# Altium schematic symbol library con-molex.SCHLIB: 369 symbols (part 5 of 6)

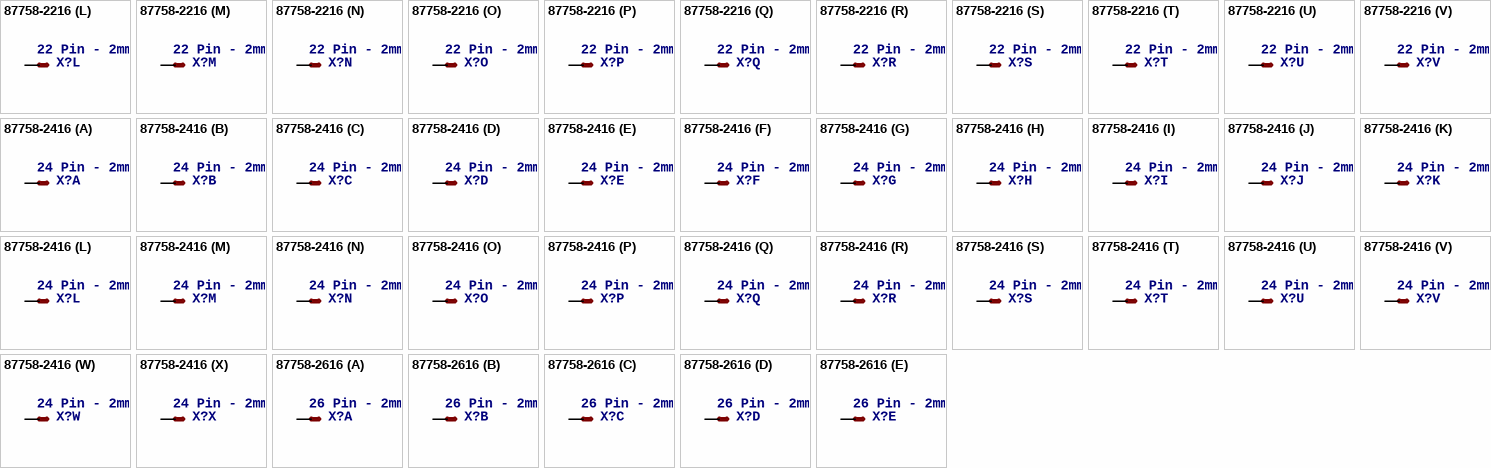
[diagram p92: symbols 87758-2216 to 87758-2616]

## 87758-2216
designator X?, comment 22 Pin - 2mm Dual Row Single Wafer, Vertical T/H HDR   Source: http://www.molex.com/pdm_docs/sd/877580616_sd.pdf
MPN: 87758-2216
footprint 87758-2216
part A pins: 1 S
part B pins: 2 S
part C pins: 3 S
part D pins: 4 S
part E pins: 5 S
part F pins: 6 S
part G pins: 7 S
part H pins: 8 S
part I pins: 9 S
part J pins: 10 S
part K pins: 11 S
part L pins: 12 S
part M pins: 13 S
part N pins: 14 S
part O pins: 15 S
part P pins: 16 S
part Q pins: 17 S
part R pins: 18 S
part S pins: 19 S
part T pins: 20 S
part U pins: 21 S
part V pins: 22 S

## 87758-2416
designator X?, comment 24 Pin - 2mm Dual Row Single Wafer, Vertical T/H HDR   Source: http://www.molex.com/pdm_docs/sd/877580616_sd.pdf
MPN: 87758-2416
footprint 87758-2416
part A pins: 1 S
part B pins: 2 S
part C pins: 3 S
part D pins: 4 S
part E pins: 5 S
part F pins: 6 S
part G pins: 7 S
part H pins: 8 S
part I pins: 9 S
part J pins: 10 S
part K pins: 11 S
part L pins: 12 S
part M pins: 13 S
part N pins: 14 S
part O pins: 15 S
part P pins: 16 S
part Q pins: 17 S
part R pins: 18 S
part S pins: 19 S
part T pins: 20 S
part U pins: 21 S
part V pins: 22 S
part W pins: 23 S
part X pins: 24 S

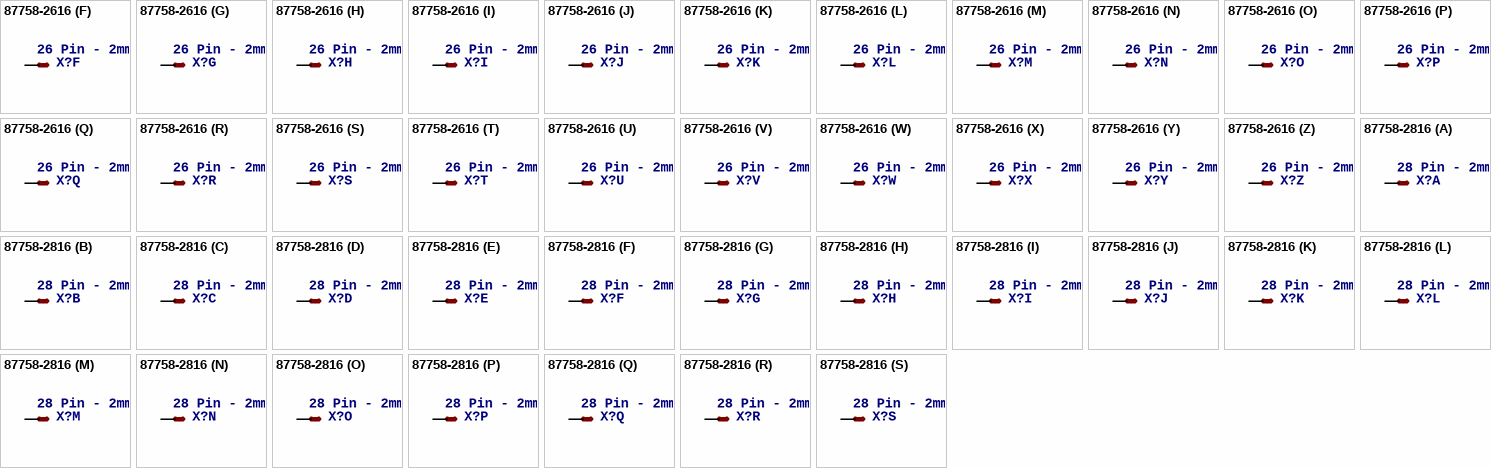
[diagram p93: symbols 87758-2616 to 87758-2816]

## 87758-2616
designator X?, comment 26 Pin - 2mm Dual Row Single Wafer, Vertical T/H HDR   Source: http://www.molex.com/pdm_docs/sd/877580616_sd.pdf
MPN: 87758-2616
footprint 87758-2616
part A pins: 1 S
part B pins: 2 S
part C pins: 3 S
part D pins: 4 S
part E pins: 5 S
part F pins: 6 S
part G pins: 7 S
part H pins: 8 S
part I pins: 9 S
part J pins: 10 S
part K pins: 11 S
part L pins: 12 S
part M pins: 13 S
part N pins: 14 S
part O pins: 15 S
part P pins: 16 S
part Q pins: 17 S
part R pins: 18 S
part S pins: 19 S
part T pins: 20 S
part U pins: 21 S
part V pins: 22 S
part W pins: 23 S
part X pins: 24 S
part Y pins: 25 S
part Z pins: 26 S

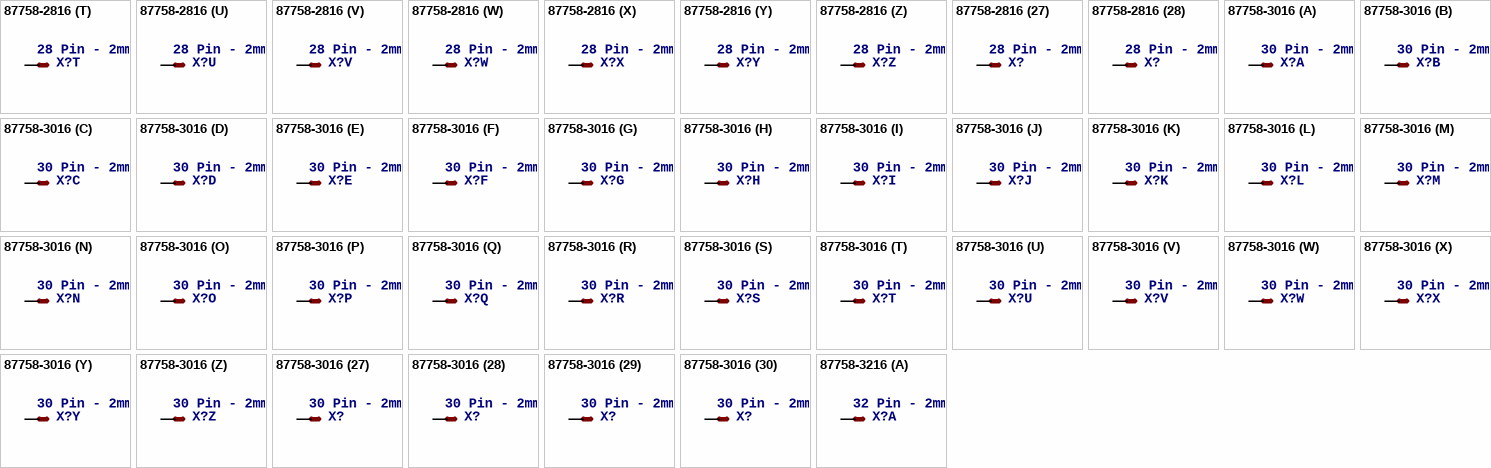
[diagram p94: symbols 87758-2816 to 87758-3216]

## 87758-2816
designator X?, comment 28 Pin - 2mm Dual Row Single Wafer, Vertical T/H HDR   Source: http://www.molex.com/pdm_docs/sd/877580616_sd.pdf
MPN: 87758-2816
footprint 87758-2816
part A pins: 1 S
part B pins: 2 S
part C pins: 3 S
part D pins: 4 S
part E pins: 5 S
part F pins: 6 S
part G pins: 7 S
part H pins: 8 S
part I pins: 9 S
part J pins: 10 S
part K pins: 11 S
part L pins: 12 S
part M pins: 13 S
part N pins: 14 S
part O pins: 15 S
part P pins: 16 S
part Q pins: 17 S
part R pins: 18 S
part S pins: 19 S
part T pins: 20 S
part U pins: 21 S
part V pins: 22 S
part W pins: 23 S
part X pins: 24 S
part Y pins: 25 S
part Z pins: 26 S
part 27 pins: 27 S
part 28 pins: 28 S

## 87758-3016
designator X?, comment 30 Pin - 2mm Dual Row Single Wafer, Vertical T/H HDR   Source: http://www.molex.com/pdm_docs/sd/877580616_sd.pdf
MPN: 87758-3016; MF: MOLEX
footprint 87758-3016
part A pins: 1 S
part B pins: 2 S
part C pins: 3 S
part D pins: 4 S
part E pins: 5 S
part F pins: 6 S
part G pins: 7 S
part H pins: 8 S
part I pins: 9 S
part J pins: 10 S
part K pins: 11 S
part L pins: 12 S
part M pins: 13 S
part N pins: 14 S
part O pins: 15 S
part P pins: 16 S
part Q pins: 17 S
part R pins: 18 S
part S pins: 19 S
part T pins: 20 S
part U pins: 21 S
part V pins: 22 S
part W pins: 23 S
part X pins: 24 S
part Y pins: 25 S
part Z pins: 26 S
part 27 pins: 27 S
part 28 pins: 28 S
part 29 pins: 29 S
part 30 pins: 30 S

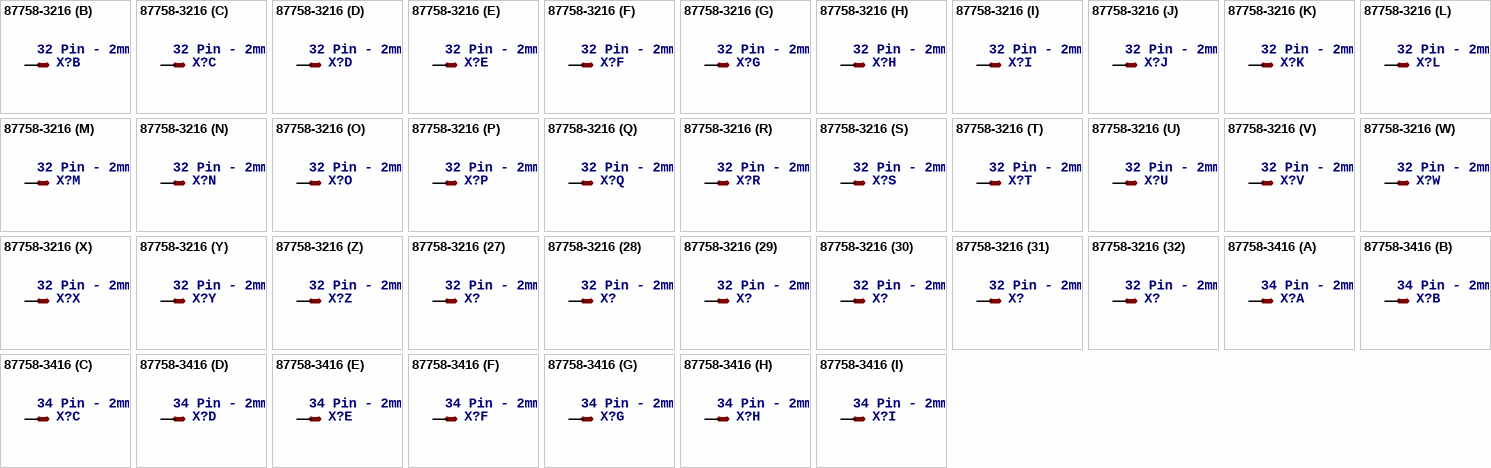
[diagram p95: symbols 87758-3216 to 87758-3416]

## 87758-3216
designator X?, comment 32 Pin - 2mm Dual Row Single Wafer, Vertical T/H HDR   Source: http://www.molex.com/pdm_docs/sd/877580616_sd.pdf
MPN: 87758-3216
footprint 87758-3216
part A pins: 1 S
part B pins: 2 S
part C pins: 3 S
part D pins: 4 S
part E pins: 5 S
part F pins: 6 S
part G pins: 7 S
part H pins: 8 S
part I pins: 9 S
part J pins: 10 S
part K pins: 11 S
part L pins: 12 S
part M pins: 13 S
part N pins: 14 S
part O pins: 15 S
part P pins: 16 S
part Q pins: 17 S
part R pins: 18 S
part S pins: 19 S
part T pins: 20 S
part U pins: 21 S
part V pins: 22 S
part W pins: 23 S
part X pins: 24 S
part Y pins: 25 S
part Z pins: 26 S
part 27 pins: 27 S
part 28 pins: 28 S
part 29 pins: 29 S
part 30 pins: 30 S
part 31 pins: 31 S
part 32 pins: 32 S

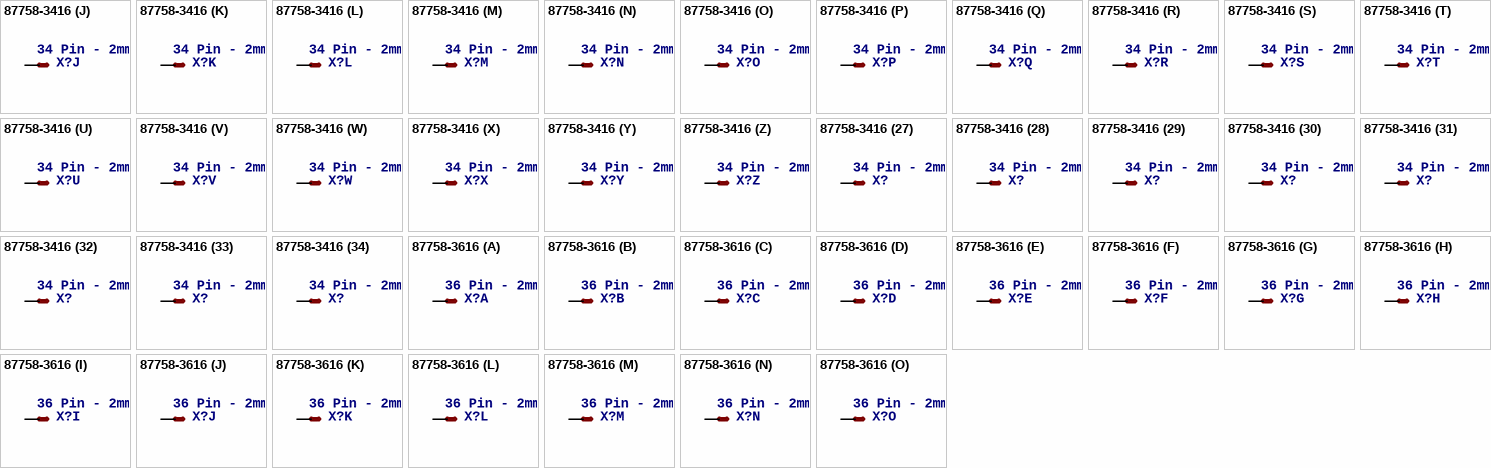
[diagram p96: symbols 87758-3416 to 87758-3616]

## 87758-3416
designator X?, comment 34 Pin - 2mm Dual Row Single Wafer, Vertical T/H HDR   Source: http://www.molex.com/pdm_docs/sd/877580616_sd.pdf
MPN: 87758-3416
footprint 87758-3416
part A pins: 1 S
part B pins: 2 S
part C pins: 3 S
part D pins: 4 S
part E pins: 5 S
part F pins: 6 S
part G pins: 7 S
part H pins: 8 S
part I pins: 9 S
part J pins: 10 S
part K pins: 11 S
part L pins: 12 S
part M pins: 13 S
part N pins: 14 S
part O pins: 15 S
part P pins: 16 S
part Q pins: 17 S
part R pins: 18 S
part S pins: 19 S
part T pins: 20 S
part U pins: 21 S
part V pins: 22 S
part W pins: 23 S
part X pins: 24 S
part Y pins: 25 S
part Z pins: 26 S
part 27 pins: 27 S
part 28 pins: 28 S
part 29 pins: 29 S
part 30 pins: 30 S
part 31 pins: 31 S
part 32 pins: 32 S
part 33 pins: 33 S
part 34 pins: 34 S

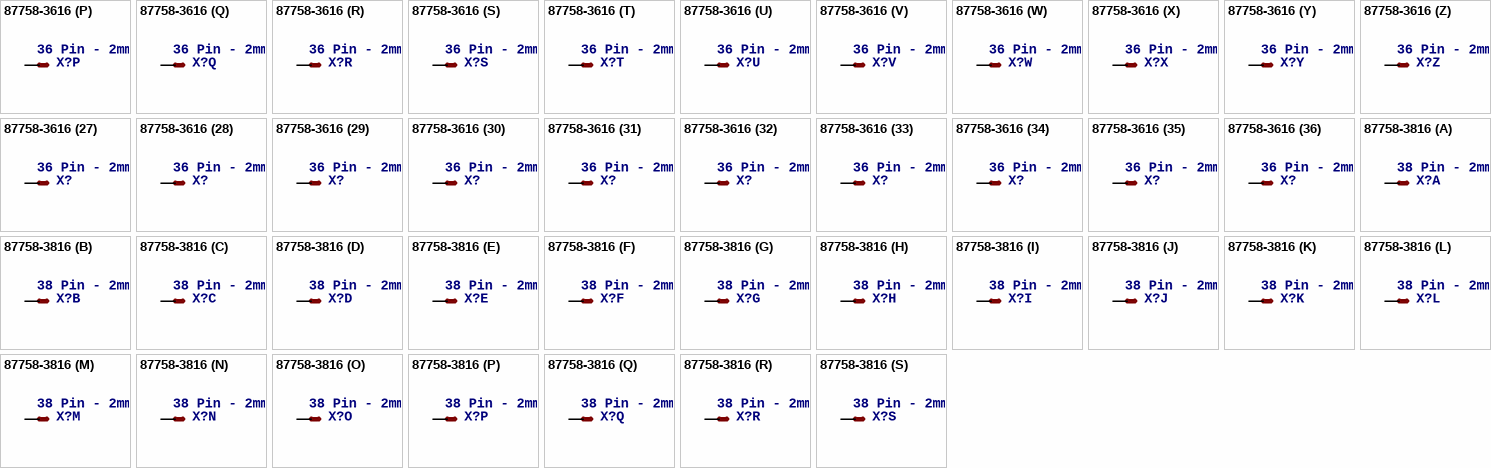
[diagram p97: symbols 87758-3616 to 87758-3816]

## 87758-3616
designator X?, comment 36 Pin - 2mm Dual Row Single Wafer, Vertical T/H HDR   Source: http://www.molex.com/pdm_docs/sd/877580616_sd.pdf
MPN: 87758-3616
footprint 87758-3616
part A pins: 1 S
part B pins: 2 S
part C pins: 3 S
part D pins: 4 S
part E pins: 5 S
part F pins: 6 S
part G pins: 7 S
part H pins: 8 S
part I pins: 9 S
part J pins: 10 S
part K pins: 11 S
part L pins: 12 S
part M pins: 13 S
part N pins: 14 S
part O pins: 15 S
part P pins: 16 S
part Q pins: 17 S
part R pins: 18 S
part S pins: 19 S
part T pins: 20 S
part U pins: 21 S
part V pins: 22 S
part W pins: 23 S
part X pins: 24 S
part Y pins: 25 S
part Z pins: 26 S
part 27 pins: 27 S
part 28 pins: 28 S
part 29 pins: 29 S
part 30 pins: 30 S
part 31 pins: 31 S
part 32 pins: 32 S
part 33 pins: 33 S
part 34 pins: 34 S
part 35 pins: 35 S
part 36 pins: 36 S

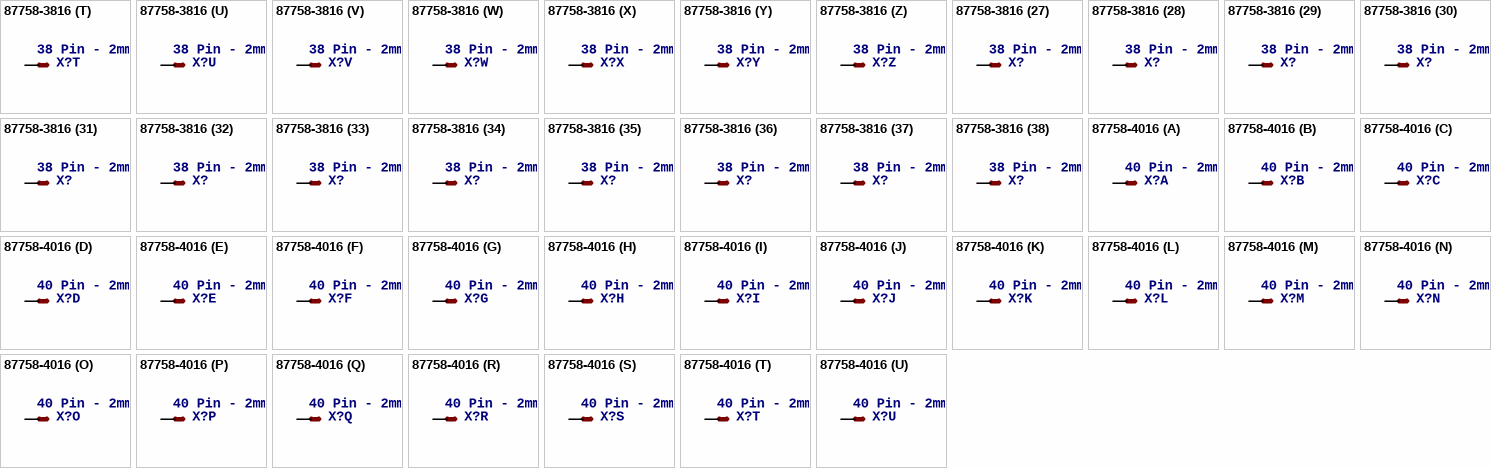
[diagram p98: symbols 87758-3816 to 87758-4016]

## 87758-3816
designator X?, comment 38 Pin - 2mm Dual Row Single Wafer, Vertical T/H HDR   Source: http://www.molex.com/pdm_docs/sd/877580616_sd.pdf
MPN: 87758-3816
footprint 87758-3816
part A pins: 1 S
part B pins: 2 S
part C pins: 3 S
part D pins: 4 S
part E pins: 5 S
part F pins: 6 S
part G pins: 7 S
part H pins: 8 S
part I pins: 9 S
part J pins: 10 S
part K pins: 11 S
part L pins: 12 S
part M pins: 13 S
part N pins: 14 S
part O pins: 15 S
part P pins: 16 S
part Q pins: 17 S
part R pins: 18 S
part S pins: 19 S
part T pins: 20 S
part U pins: 21 S
part V pins: 22 S
part W pins: 23 S
part X pins: 24 S
part Y pins: 25 S
part Z pins: 26 S
part 27 pins: 27 S
part 28 pins: 28 S
part 29 pins: 29 S
part 30 pins: 30 S
part 31 pins: 31 S
part 32 pins: 32 S
part 33 pins: 33 S
part 34 pins: 34 S
part 35 pins: 35 S
part 36 pins: 36 S
part 37 pins: 37 S
part 38 pins: 38 S

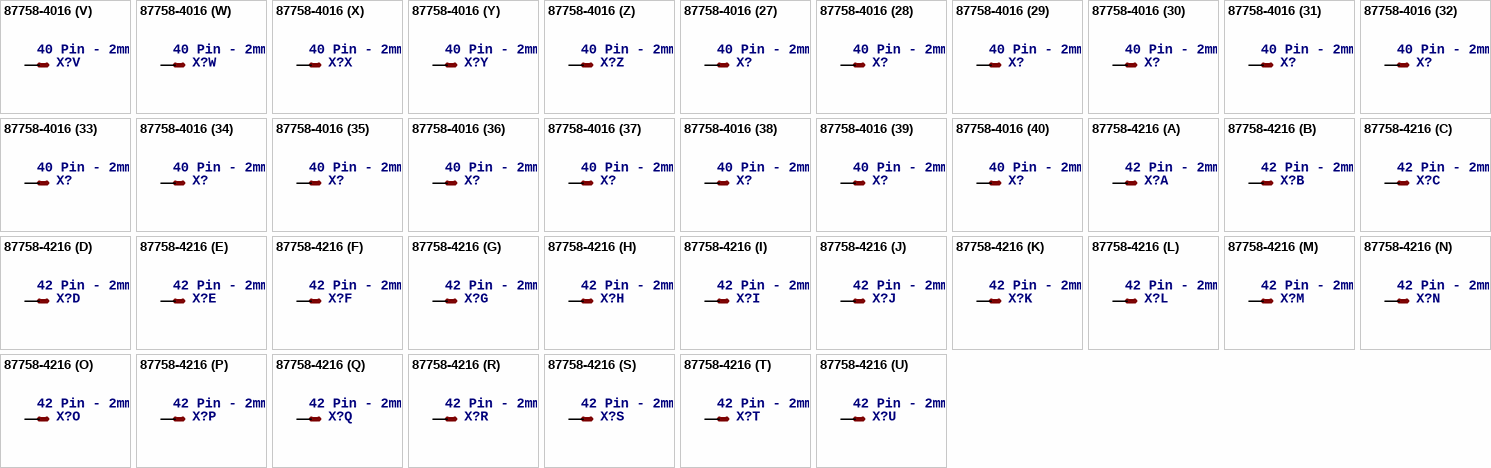
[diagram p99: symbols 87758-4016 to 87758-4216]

## 87758-4016
designator X?, comment 40 Pin - 2mm Dual Row Single Wafer, Vertical T/H HDR   Source: http://www.molex.com/pdm_docs/sd/877580616_sd.pdf
MPN: 87758-4016
footprint 87758-4016
part A pins: 1 S
part B pins: 2 S
part C pins: 3 S
part D pins: 4 S
part E pins: 5 S
part F pins: 6 S
part G pins: 7 S
part H pins: 8 S
part I pins: 9 S
part J pins: 10 S
part K pins: 11 S
part L pins: 12 S
part M pins: 13 S
part N pins: 14 S
part O pins: 15 S
part P pins: 16 S
part Q pins: 17 S
part R pins: 18 S
part S pins: 19 S
part T pins: 20 S
part U pins: 21 S
part V pins: 22 S
part W pins: 23 S
part X pins: 24 S
part Y pins: 25 S
part Z pins: 26 S
part 27 pins: 27 S
part 28 pins: 28 S
part 29 pins: 29 S
part 30 pins: 30 S
part 31 pins: 31 S
part 32 pins: 32 S
part 33 pins: 33 S
part 34 pins: 34 S
part 35 pins: 35 S
part 36 pins: 36 S
part 37 pins: 37 S
part 38 pins: 38 S
part 39 pins: 39 S
part 40 pins: 40 S

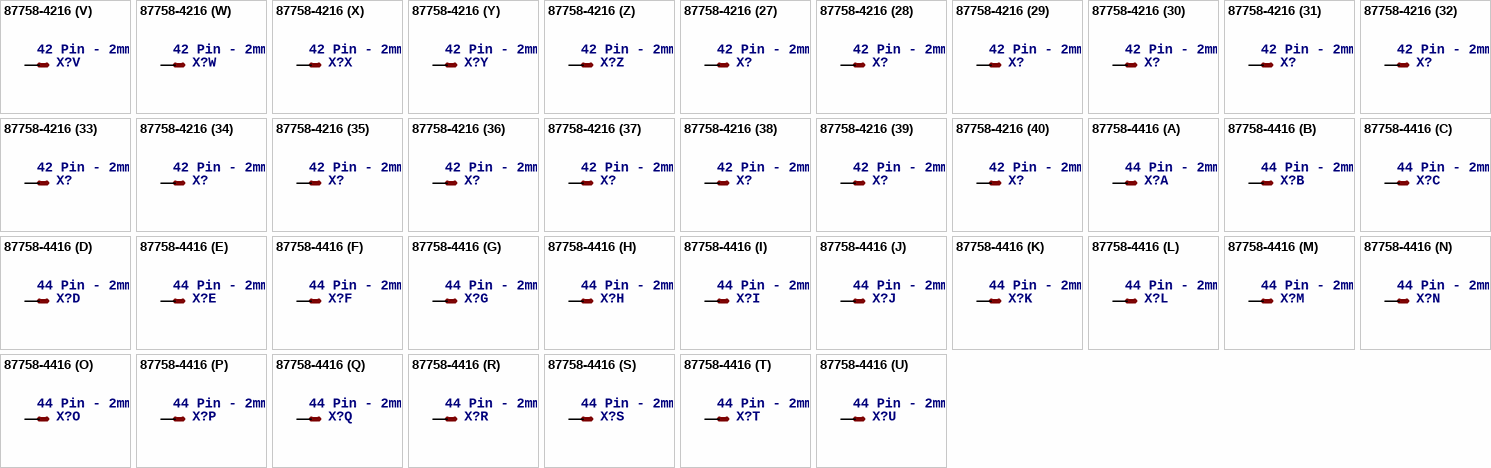
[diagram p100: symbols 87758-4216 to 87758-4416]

## 87758-4216
designator X?, comment 42 Pin - 2mm Dual Row Single Wafer, Vertical T/H HDR   Source: http://www.molex.com/pdm_docs/sd/877580616_sd.pdf
MPN: 87758-4216
footprint 87758-4216
part A pins: 1 S
part B pins: 2 S
part C pins: 3 S
part D pins: 4 S
part E pins: 5 S
part F pins: 6 S
part G pins: 7 S
part H pins: 8 S
part I pins: 9 S
part J pins: 10 S
part K pins: 11 S
part L pins: 12 S
part M pins: 13 S
part N pins: 14 S
part O pins: 15 S
part P pins: 16 S
part Q pins: 17 S
part R pins: 18 S
part S pins: 19 S
part T pins: 20 S
part U pins: 21 S
part V pins: 22 S
part W pins: 23 S
part X pins: 24 S
part Y pins: 25 S
part Z pins: 26 S
part 27 pins: 27 S
part 28 pins: 28 S
part 29 pins: 29 S
part 30 pins: 30 S
part 31 pins: 31 S
part 32 pins: 32 S
part 33 pins: 33 S
part 34 pins: 34 S
part 35 pins: 35 S
part 36 pins: 36 S
part 37 pins: 37 S
part 38 pins: 38 S
part 39 pins: 39 S
part 40 pins: 40 S
part 41 pins: 41 S
part 42 pins: 42 S

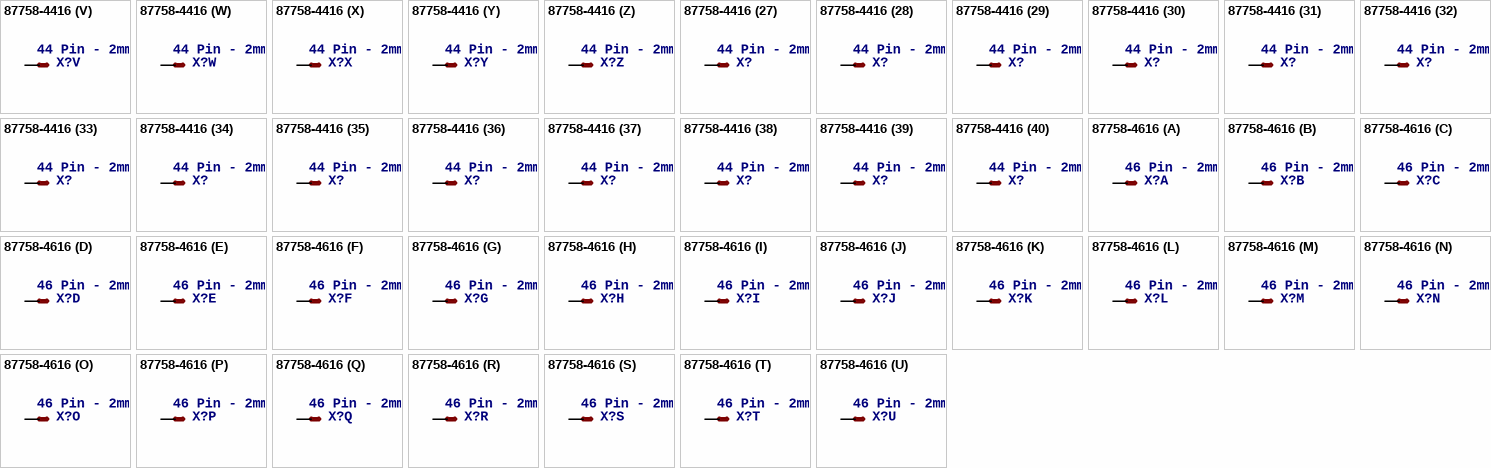
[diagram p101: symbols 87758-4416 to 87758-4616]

## 87758-4416
designator X?, comment 44 Pin - 2mm Dual Row Single Wafer, Vertical T/H HDR   Source: http://www.molex.com/pdm_docs/sd/877580616_sd.pdf
MPN: 87758-4416; MF: MOLEX
footprint 87758-4416
part A pins: 1 S
part B pins: 2 S
part C pins: 3 S
part D pins: 4 S
part E pins: 5 S
part F pins: 6 S
part G pins: 7 S
part H pins: 8 S
part I pins: 9 S
part J pins: 10 S
part K pins: 11 S
part L pins: 12 S
part M pins: 13 S
part N pins: 14 S
part O pins: 15 S
part P pins: 16 S
part Q pins: 17 S
part R pins: 18 S
part S pins: 19 S
part T pins: 20 S
part U pins: 21 S
part V pins: 22 S
part W pins: 23 S
part X pins: 24 S
part Y pins: 25 S
part Z pins: 26 S
part 27 pins: 27 S
part 28 pins: 28 S
part 29 pins: 29 S
part 30 pins: 30 S
part 31 pins: 31 S
part 32 pins: 32 S
part 33 pins: 33 S
part 34 pins: 34 S
part 35 pins: 35 S
part 36 pins: 36 S
part 37 pins: 37 S
part 38 pins: 38 S
part 39 pins: 39 S
part 40 pins: 40 S
part 41 pins: 41 S
part 42 pins: 42 S
part 43 pins: 43 S
part 44 pins: 44 S

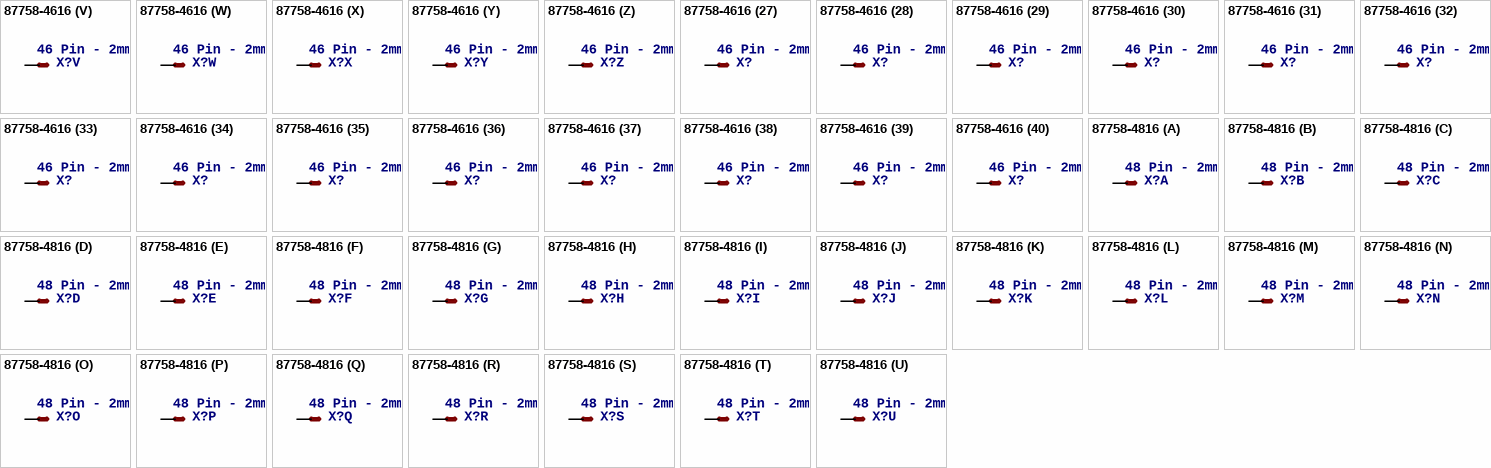
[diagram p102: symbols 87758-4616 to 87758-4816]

## 87758-4616
designator X?, comment 46 Pin - 2mm Dual Row Single Wafer, Vertical T/H HDR   Source: http://www.molex.com/pdm_docs/sd/877580616_sd.pdf
MPN: 87758-4616
footprint 87758-4616
part A pins: 1 S
part B pins: 2 S
part C pins: 3 S
part D pins: 4 S
part E pins: 5 S
part F pins: 6 S
part G pins: 7 S
part H pins: 8 S
part I pins: 9 S
part J pins: 10 S
part K pins: 11 S
part L pins: 12 S
part M pins: 13 S
part N pins: 14 S
part O pins: 15 S
part P pins: 16 S
part Q pins: 17 S
part R pins: 18 S
part S pins: 19 S
part T pins: 20 S
part U pins: 21 S
part V pins: 22 S
part W pins: 23 S
part X pins: 24 S
part Y pins: 25 S
part Z pins: 26 S
part 27 pins: 27 S
part 28 pins: 28 S
part 29 pins: 29 S
part 30 pins: 30 S
part 31 pins: 31 S
part 32 pins: 32 S
part 33 pins: 33 S
part 34 pins: 34 S
part 35 pins: 35 S
part 36 pins: 36 S
part 37 pins: 37 S
part 38 pins: 38 S
part 39 pins: 39 S
part 40 pins: 40 S
part 41 pins: 41 S
part 42 pins: 42 S
part 43 pins: 43 S
part 44 pins: 44 S
part 45 pins: 45 S
part 46 pins: 46 S

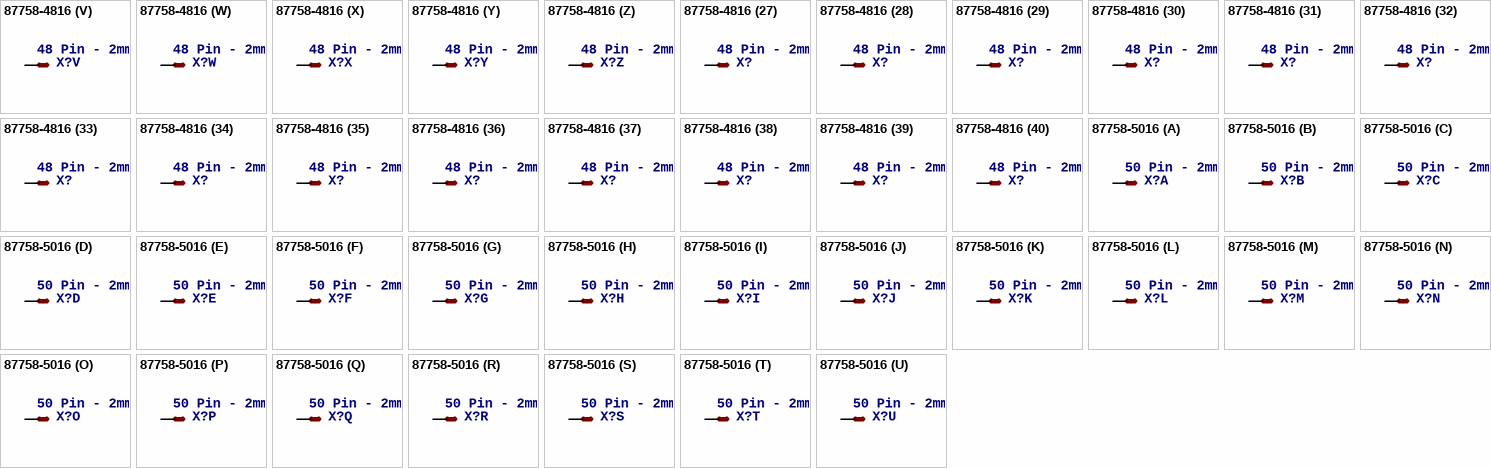
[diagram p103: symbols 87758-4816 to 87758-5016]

## 87758-4816
designator X?, comment 48 Pin - 2mm Dual Row Single Wafer, Vertical T/H HDR   Source: http://www.molex.com/pdm_docs/sd/877580616_sd.pdf
MPN: 87758-4816
footprint 87758-4816
part A pins: 1 S
part B pins: 2 S
part C pins: 3 S
part D pins: 4 S
part E pins: 5 S
part F pins: 6 S
part G pins: 7 S
part H pins: 8 S
part I pins: 9 S
part J pins: 10 S
part K pins: 11 S
part L pins: 12 S
part M pins: 13 S
part N pins: 14 S
part O pins: 15 S
part P pins: 16 S
part Q pins: 17 S
part R pins: 18 S
part S pins: 19 S
part T pins: 20 S
part U pins: 21 S
part V pins: 22 S
part W pins: 23 S
part X pins: 24 S
part Y pins: 25 S
part Z pins: 26 S
part 27 pins: 27 S
part 28 pins: 28 S
part 29 pins: 29 S
part 30 pins: 30 S
part 31 pins: 31 S
part 32 pins: 32 S
part 33 pins: 33 S
part 34 pins: 34 S
part 35 pins: 35 S
part 36 pins: 36 S
part 37 pins: 37 S
part 38 pins: 38 S
part 39 pins: 39 S
part 40 pins: 40 S
part 41 pins: 41 S
part 42 pins: 42 S
part 43 pins: 43 S
part 44 pins: 44 S
part 45 pins: 45 S
part 46 pins: 46 S
part 47 pins: 47 S
part 48 pins: 48 S

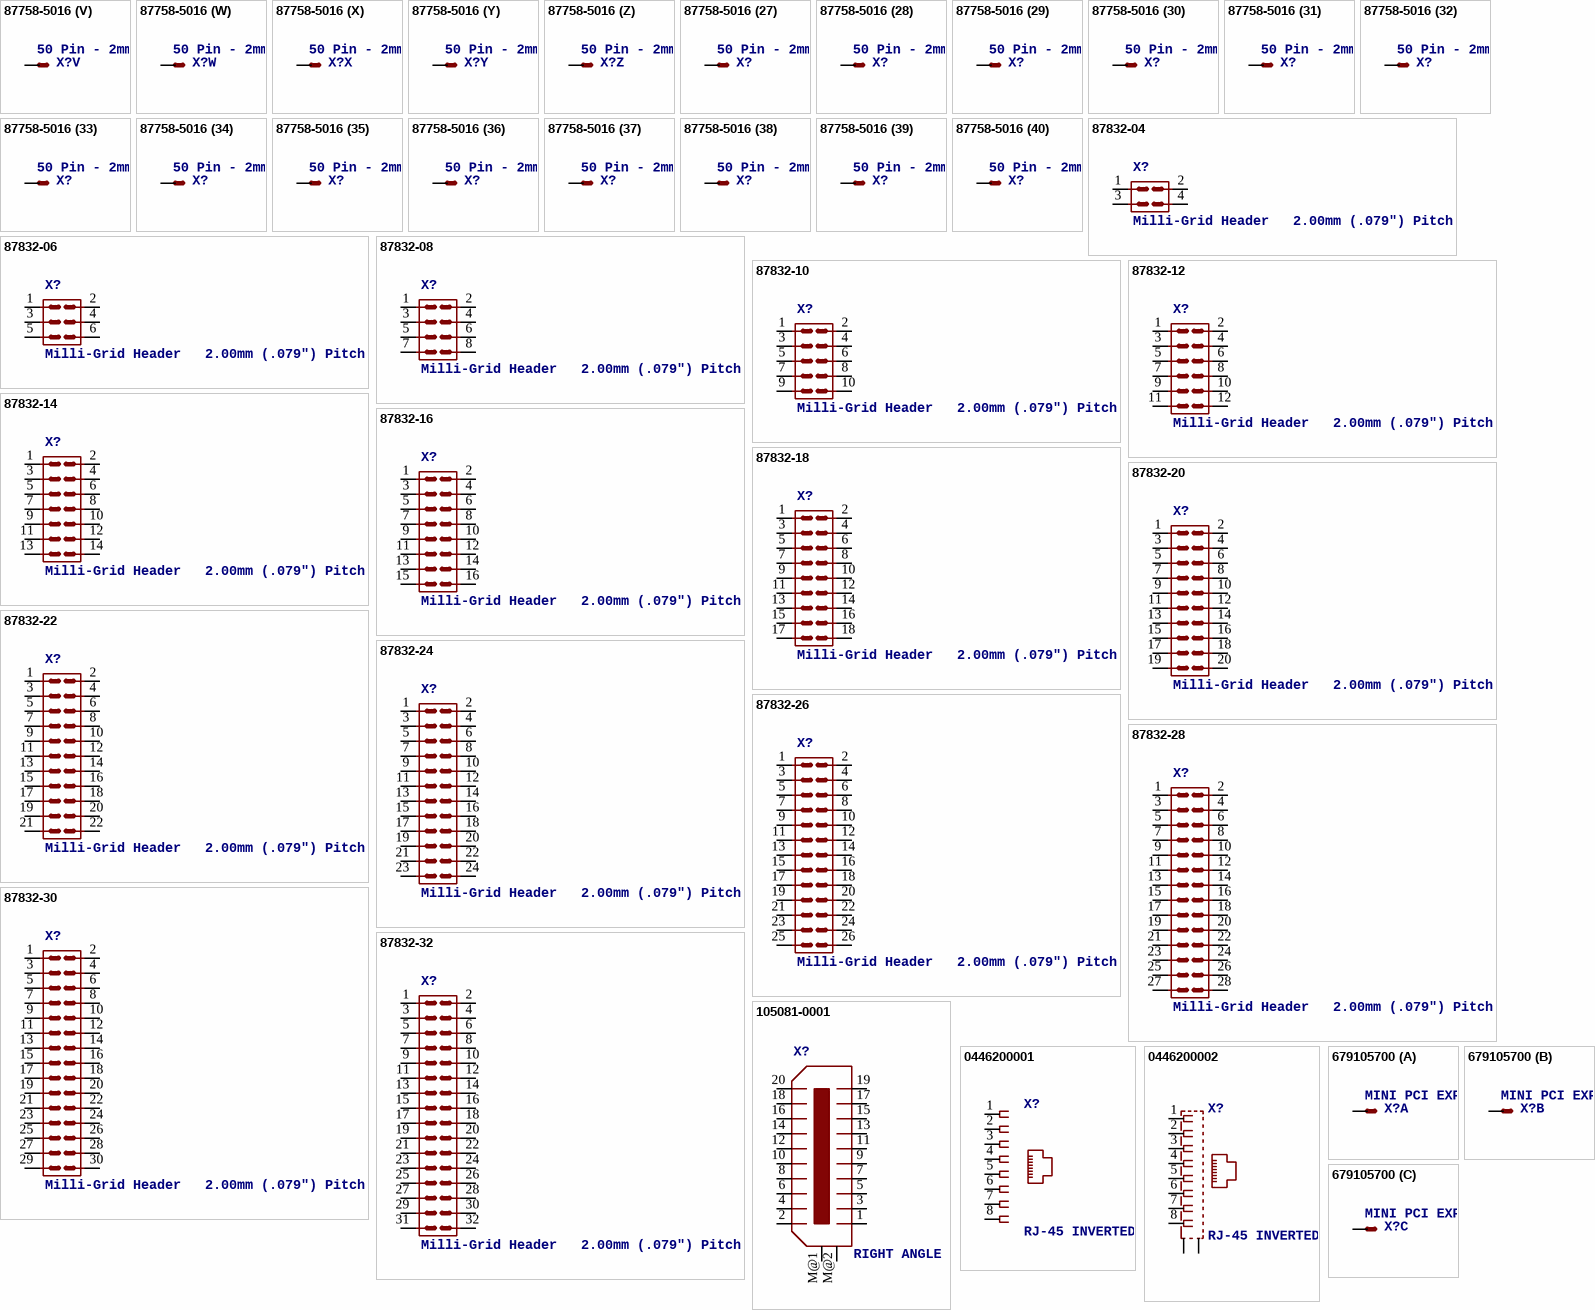
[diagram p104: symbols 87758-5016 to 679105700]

## 87758-5016
designator X?, comment 50 Pin - 2mm Dual Row Single Wafer, Vertical T/H HDR   Source: http://www.molex.com/pdm_docs/sd/877580616_sd.pdf
MPN: 87758-5016; MF: MOLEX
footprint 87758-5016
part A pins: 1 S
part B pins: 2 S
part C pins: 3 S
part D pins: 4 S
part E pins: 5 S
part F pins: 6 S
part G pins: 7 S
part H pins: 8 S
part I pins: 9 S
part J pins: 10 S
part K pins: 11 S
part L pins: 12 S
part M pins: 13 S
part N pins: 14 S
part O pins: 15 S
part P pins: 16 S
part Q pins: 17 S
part R pins: 18 S
part S pins: 19 S
part T pins: 20 S
part U pins: 21 S
part V pins: 22 S
part W pins: 23 S
part X pins: 24 S
part Y pins: 25 S
part Z pins: 26 S
part 27 pins: 27 S
part 28 pins: 28 S
part 29 pins: 29 S
part 30 pins: 30 S
part 31 pins: 31 S
part 32 pins: 32 S
part 33 pins: 33 S
part 34 pins: 34 S
part 35 pins: 35 S
part 36 pins: 36 S
part 37 pins: 37 S
part 38 pins: 38 S
part 39 pins: 39 S
part 40 pins: 40 S
part 41 pins: 41 S
part 42 pins: 42 S
part 43 pins: 43 S
part 44 pins: 44 S
part 45 pins: 45 S
part 46 pins: 46 S
part 47 pins: 47 S
part 48 pins: 48 S
part 49 pins: 49 S
part 50 pins: 50 S

## 87832-04
designator X?, comment Milli-Grid Header   2.00mm (.079") Pitch
footprint 87832-04
pins: 1, 2, 3, 4

## 87832-06
designator X?, comment Milli-Grid Header   2.00mm (.079") Pitch
footprint 87832-06
pins: 1, 2, 3, 4, 5, 6

## 87832-08
designator X?, comment Milli-Grid Header   2.00mm (.079") Pitch
footprint 87832-08
pins: 1, 2, 3, 4, 5, 6, 7, 8

## 87832-10
designator X?, comment Milli-Grid Header   2.00mm (.079") Pitch
footprint 87832-10
pins: 1, 2, 3, 4, 5, 6, 7, 8, 9, 10

## 87832-12
designator X?, comment Milli-Grid Header   2.00mm (.079") Pitch
footprint 87832-12
pins: 1, 2, 3, 4, 5, 6, 7, 8, 9, 10, 11, 12

## 87832-14
designator X?, comment Milli-Grid Header   2.00mm (.079") Pitch
footprint 87832-14
pins: 1, 2, 3, 4, 5, 6, 7, 8, 9, 10, 11, 12, 13, 14

## 87832-16
designator X?, comment Milli-Grid Header   2.00mm (.079") Pitch
footprint 87832-16
pins: 1, 2, 3, 4, 5, 6, 7, 8, 9, 10, 11, 12, 13, 14, 15, 16

## 87832-18
designator X?, comment Milli-Grid Header   2.00mm (.079") Pitch
footprint 87832-18
pins: 1, 2, 3, 4, 5, 6, 7, 8, 9, 10, 11, 12, 13, 14, 15, 16, 17, 18

## 87832-20
designator X?, comment Milli-Grid Header   2.00mm (.079") Pitch
footprint 87832-20
pins: 1, 2, 3, 4, 5, 6, 7, 8, 9, 10, 11, 12, 13, 14, 15, 16, 17, 18, 19, 20

## 87832-22
designator X?, comment Milli-Grid Header   2.00mm (.079") Pitch
footprint 87832-22
pins: 1, 2, 3, 4, 5, 6, 7, 8, 9, 10, 11, 12, 13, 14, 15, 16, 17, 18, 19, 20, 21, 22

## 87832-24
designator X?, comment Milli-Grid Header   2.00mm (.079") Pitch
footprint 87832-24
pins: 1, 2, 3, 4, 5, 6, 7, 8, 9, 10, 11, 12, 13, 14, 15, 16, 17, 18, 19, 20, 21, 22, 23, 24

## 87832-26
designator X?, comment Milli-Grid Header   2.00mm (.079") Pitch
footprint 87832-26
pins: 1, 2, 3, 4, 5, 6, 7, 8, 9, 10, 11, 12, 13, 14, 15, 16, 17, 18, 19, 20, 21, 22, 23, 24, 25, 26

## 87832-28
designator X?, comment Milli-Grid Header   2.00mm (.079") Pitch
MPN: 87832-2821
footprint 87832-28
pins: 1, 2, 3, 4, 5, 6, 7, 8, 9, 10, 11, 12, 13, 14, 15, 16, 17, 18, 19, 20, 21, 22, 23, 24, 25, 26, 27, 28

## 87832-30
designator X?, comment Milli-Grid Header   2.00mm (.079") Pitch
footprint 87832-30
pins: 1, 2, 3, 4, 5, 6, 7, 8, 9, 10, 11, 12, 13, 14, 15, 16, 17, 18, 19, 20, 21, 22, 23, 24, 25, 26, 27, 28, 29, 30

## 87832-32
designator X?, comment Milli-Grid Header   2.00mm (.079") Pitch
footprint 87832-32
pins: 1, 2, 3, 4, 5, 6, 7, 8, 9, 10, 11, 12, 13, 14, 15, 16, 17, 18, 19, 20, 21, 22, 23, 24, 25, 26, 27, 28, 29, 30, 31, 32

## 105081-0001
designator X?, comment RIGHT ANGLE MINI-DISPLAYPORT RECEPTACLE   Source: http://www.molex.com/pdm_docs/sd/1050810001_sd.pdf
MPN: 105081-0001
footprint 105081-0001
pins: 1, 2, 3, 4, 5, 6, 7, 8, 9, 10, 11, 12, 13, 14, 15, 16, 17, 18, 19, 20, M@1, M@2

## 0446200001
designator X?, comment RJ-45 INVERTED MODULAR JACK ASSEMBLY WITH RJ-11 KEEPOUT FEATURE   Source:  Data sheet
footprint 0446200001
pins: 1, 2, 3, 4, 5, 6, 7, 8

## 0446200002
designator X?, comment RJ-45 INVERTED MODULAR JACK ASSEMBLY WITH RJ-11 KEEPOUT FEATURE   Source:  Data sheet    MOLEX  0446200002  BUCHSE, RJ45, GESCHIRMT    Source:
footprint 0446200002
pins: 1, 2, 3, 4, 5, 6, 7, 8, S@1 S1, S@2 S2

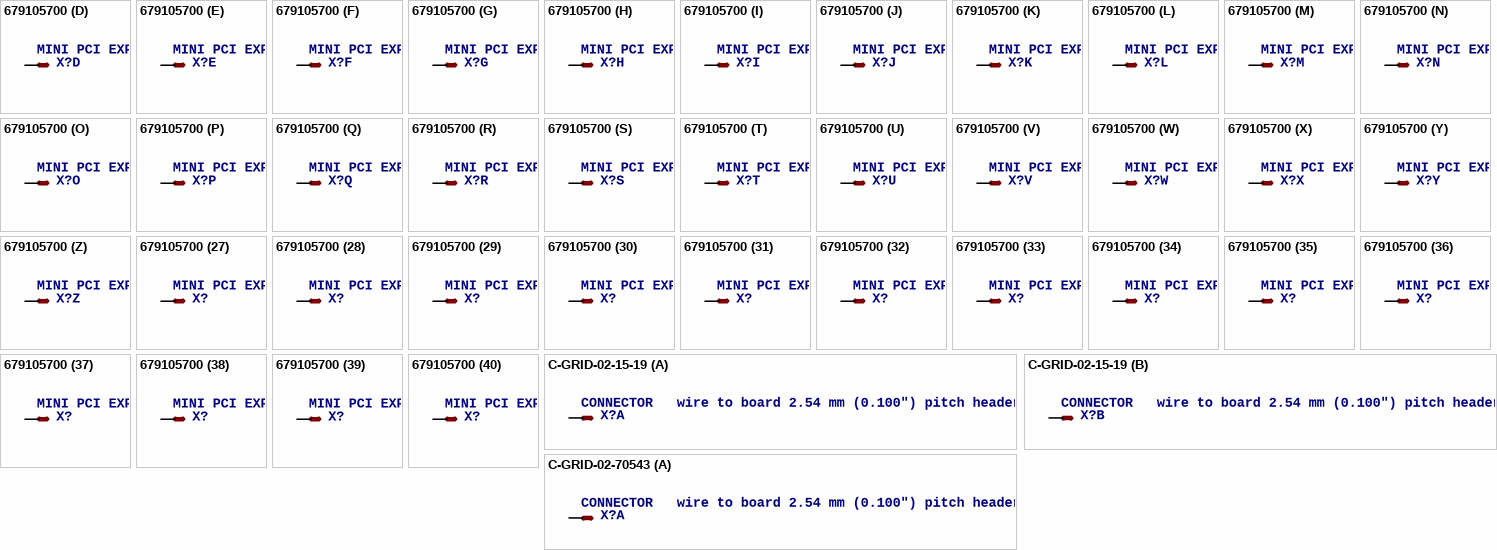
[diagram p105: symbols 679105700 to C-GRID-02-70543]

## 679105700
designator X?, comment MINI PCI EXPRESS CONNECTOR 0.8MM PITCH, 52 CIRCUIT   Source: http://www.molex.com/pdm_docs/sd/679105700_sd.pdf
MPN: 67910-5700
footprint 679105700
part A pins: 1 S
part B pins: 2 S
part C pins: 3 S
part D pins: 4 S
part E pins: 5 S
part F pins: 6 S
part G pins: 7 S
part H pins: 8 S
part I pins: 9 S
part J pins: 10 S
part K pins: 11 S
part L pins: 12 S
part M pins: 13 S
part N pins: 14 S
part O pins: 15 S
part P pins: 16 S
part Q pins: 17 S
part R pins: 18 S
part S pins: 19 S
part T pins: 20 S
part U pins: 21 S
part V pins: 22 S
part W pins: 23 S
part X pins: 24 S
part Y pins: 25 S
part Z pins: 26 S
part 27 pins: 27 S
part 28 pins: 28 S
part 29 pins: 29 S
part 30 pins: 30 S
part 31 pins: 31 S
part 32 pins: 32 S
part 33 pins: 33 S
part 34 pins: 34 S
part 35 pins: 35 S
part 36 pins: 36 S
part 37 pins: 37 S
part 38 pins: 38 S
part 39 pins: 39 S
part 40 pins: 40 S
part 41 pins: 41 S
part 42 pins: 42 S
part 43 pins: 43 S
part 44 pins: 44 S
part 45 pins: 45 S
part 46 pins: 46 S
part 47 pins: 47 S
part 48 pins: 48 S
part 49 pins: 49 S
part 50 pins: 50 S
part 51 pins: 51 S
part 52 pins: 52 S

## C-GRID-02-15-19
designator X?, comment CONNECTOR   wire to board 2.54 mm (0.100") pitch header
footprint 15-91-02
part A pins: 2 S
part B pins: 1 S

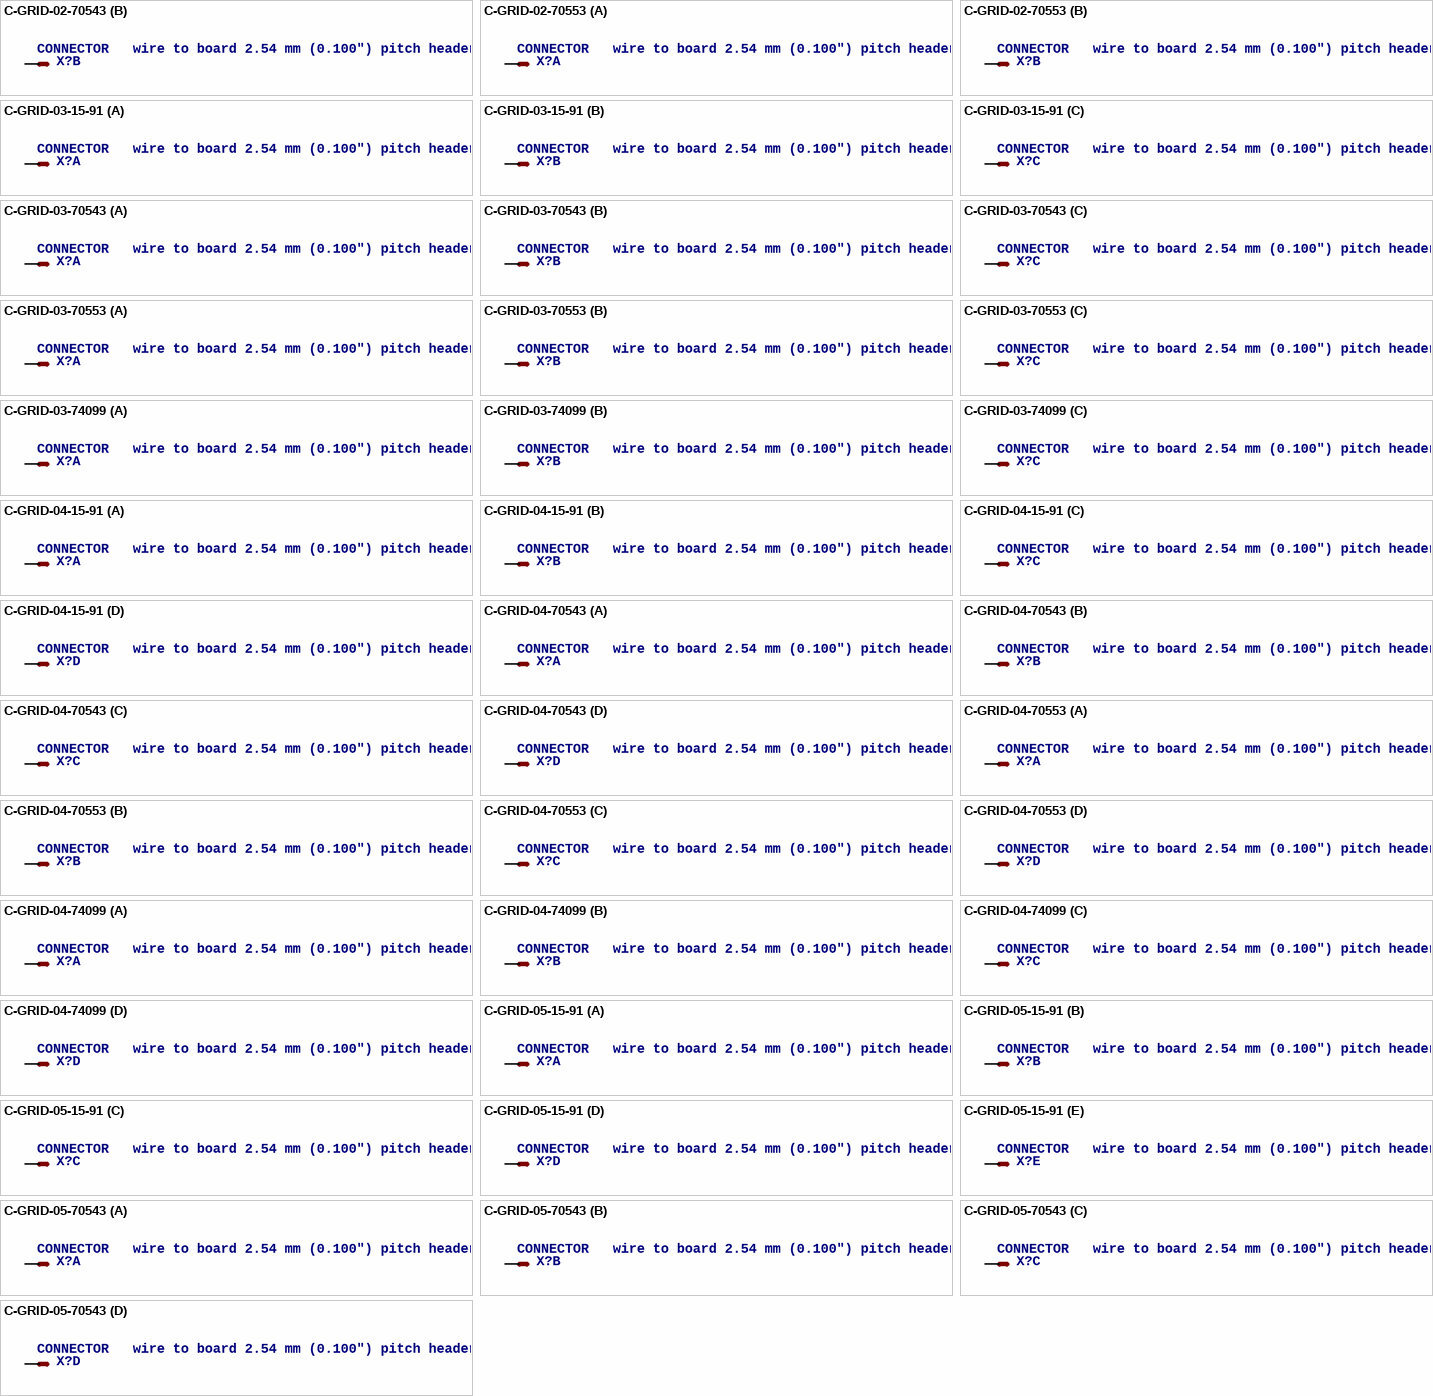
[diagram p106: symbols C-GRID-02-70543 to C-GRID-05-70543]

## C-GRID-02-70543
designator X?, comment CONNECTOR   wire to board 2.54 mm (0.100") pitch header
footprint 70543-02
part A pins: 2 S
part B pins: 1 S

## C-GRID-02-70553
designator X?, comment CONNECTOR   wire to board 2.54 mm (0.100") pitch header
footprint 70553-02
part A pins: 2 S
part B pins: 1 S

## C-GRID-03-15-91
designator X?, comment CONNECTOR   wire to board 2.54 mm (0.100") pitch header
footprint 15-91-03
part A pins: 1 S
part B pins: 2 S
part C pins: 3 S

## C-GRID-03-70543
designator X?, comment CONNECTOR   wire to board 2.54 mm (0.100") pitch header
footprint 70543-03
part A pins: 1 S
part B pins: 2 S
part C pins: 3 S

## C-GRID-03-70553
designator X?, comment CONNECTOR   wire to board 2.54 mm (0.100") pitch header
footprint 70553-03
part A pins: 1 S
part B pins: 2 S
part C pins: 3 S

## C-GRID-03-74099
designator X?, comment CONNECTOR   wire to board 2.54 mm (0.100") pitch header
footprint 74099-03
part A pins: 1 S
part B pins: 2 S
part C pins: 3 S

## C-GRID-04-15-91
designator X?, comment CONNECTOR   wire to board 2.54 mm (0.100") pitch header
footprint 15-91-04
part A pins: 1 S
part B pins: 2 S
part C pins: 3 S
part D pins: 4 S

## C-GRID-04-70543
designator X?, comment CONNECTOR   wire to board 2.54 mm (0.100") pitch header
footprint 70543-04
part A pins: 1 S
part B pins: 2 S
part C pins: 3 S
part D pins: 4 S

## C-GRID-04-70553
designator X?, comment CONNECTOR   wire to board 2.54 mm (0.100") pitch header
footprint 70553-04
part A pins: 1 S
part B pins: 2 S
part C pins: 3 S
part D pins: 4 S

## C-GRID-04-74099
designator X?, comment CONNECTOR   wire to board 2.54 mm (0.100") pitch header
footprint 74099-04
part A pins: 1 S
part B pins: 2 S
part C pins: 3 S
part D pins: 4 S

## C-GRID-05-15-91
designator X?, comment CONNECTOR   wire to board 2.54 mm (0.100") pitch header
footprint 15-91-05
part A pins: 1 S
part B pins: 2 S
part C pins: 3 S
part D pins: 4 S
part E pins: 5 S

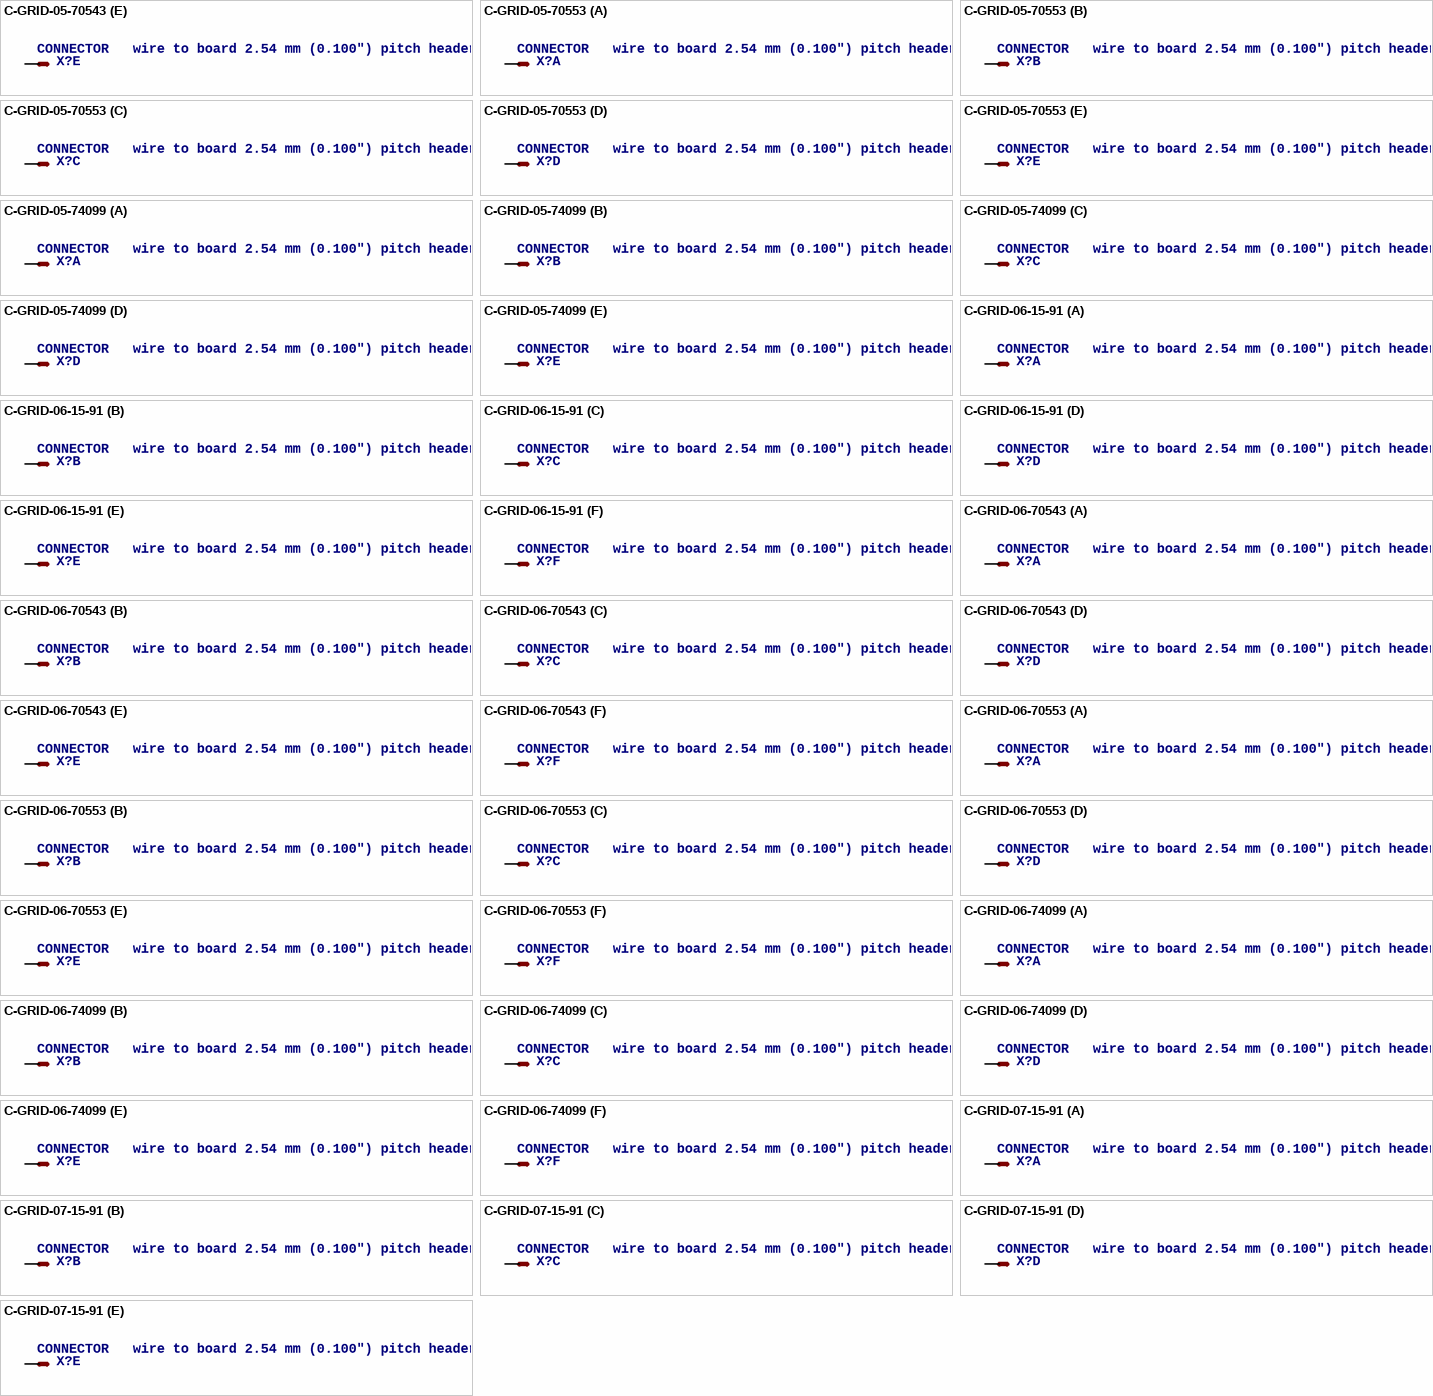
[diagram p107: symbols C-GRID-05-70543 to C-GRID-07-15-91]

## C-GRID-05-70543
designator X?, comment CONNECTOR   wire to board 2.54 mm (0.100") pitch header
footprint 70543-05
part A pins: 1 S
part B pins: 2 S
part C pins: 3 S
part D pins: 4 S
part E pins: 5 S

## C-GRID-05-70553
designator X?, comment CONNECTOR   wire to board 2.54 mm (0.100") pitch header
footprint 70553-05
part A pins: 1 S
part B pins: 2 S
part C pins: 3 S
part D pins: 4 S
part E pins: 5 S

## C-GRID-05-74099
designator X?, comment CONNECTOR   wire to board 2.54 mm (0.100") pitch header
footprint 74099-05
part A pins: 1 S
part B pins: 2 S
part C pins: 3 S
part D pins: 4 S
part E pins: 5 S

## C-GRID-06-15-91
designator X?, comment CONNECTOR   wire to board 2.54 mm (0.100") pitch header
footprint 15-91-06
part A pins: 1 S
part B pins: 2 S
part C pins: 3 S
part D pins: 4 S
part E pins: 5 S
part F pins: 6 S

## C-GRID-06-70543
designator X?, comment CONNECTOR   wire to board 2.54 mm (0.100") pitch header
footprint 70543-06
part A pins: 1 S
part B pins: 2 S
part C pins: 3 S
part D pins: 4 S
part E pins: 5 S
part F pins: 6 S

## C-GRID-06-70553
designator X?, comment CONNECTOR   wire to board 2.54 mm (0.100") pitch header
footprint 70553-06
part A pins: 1 S
part B pins: 2 S
part C pins: 3 S
part D pins: 4 S
part E pins: 5 S
part F pins: 6 S

## C-GRID-06-74099
designator X?, comment CONNECTOR   wire to board 2.54 mm (0.100") pitch header
footprint 74099-06
part A pins: 1 S
part B pins: 2 S
part C pins: 3 S
part D pins: 4 S
part E pins: 5 S
part F pins: 6 S

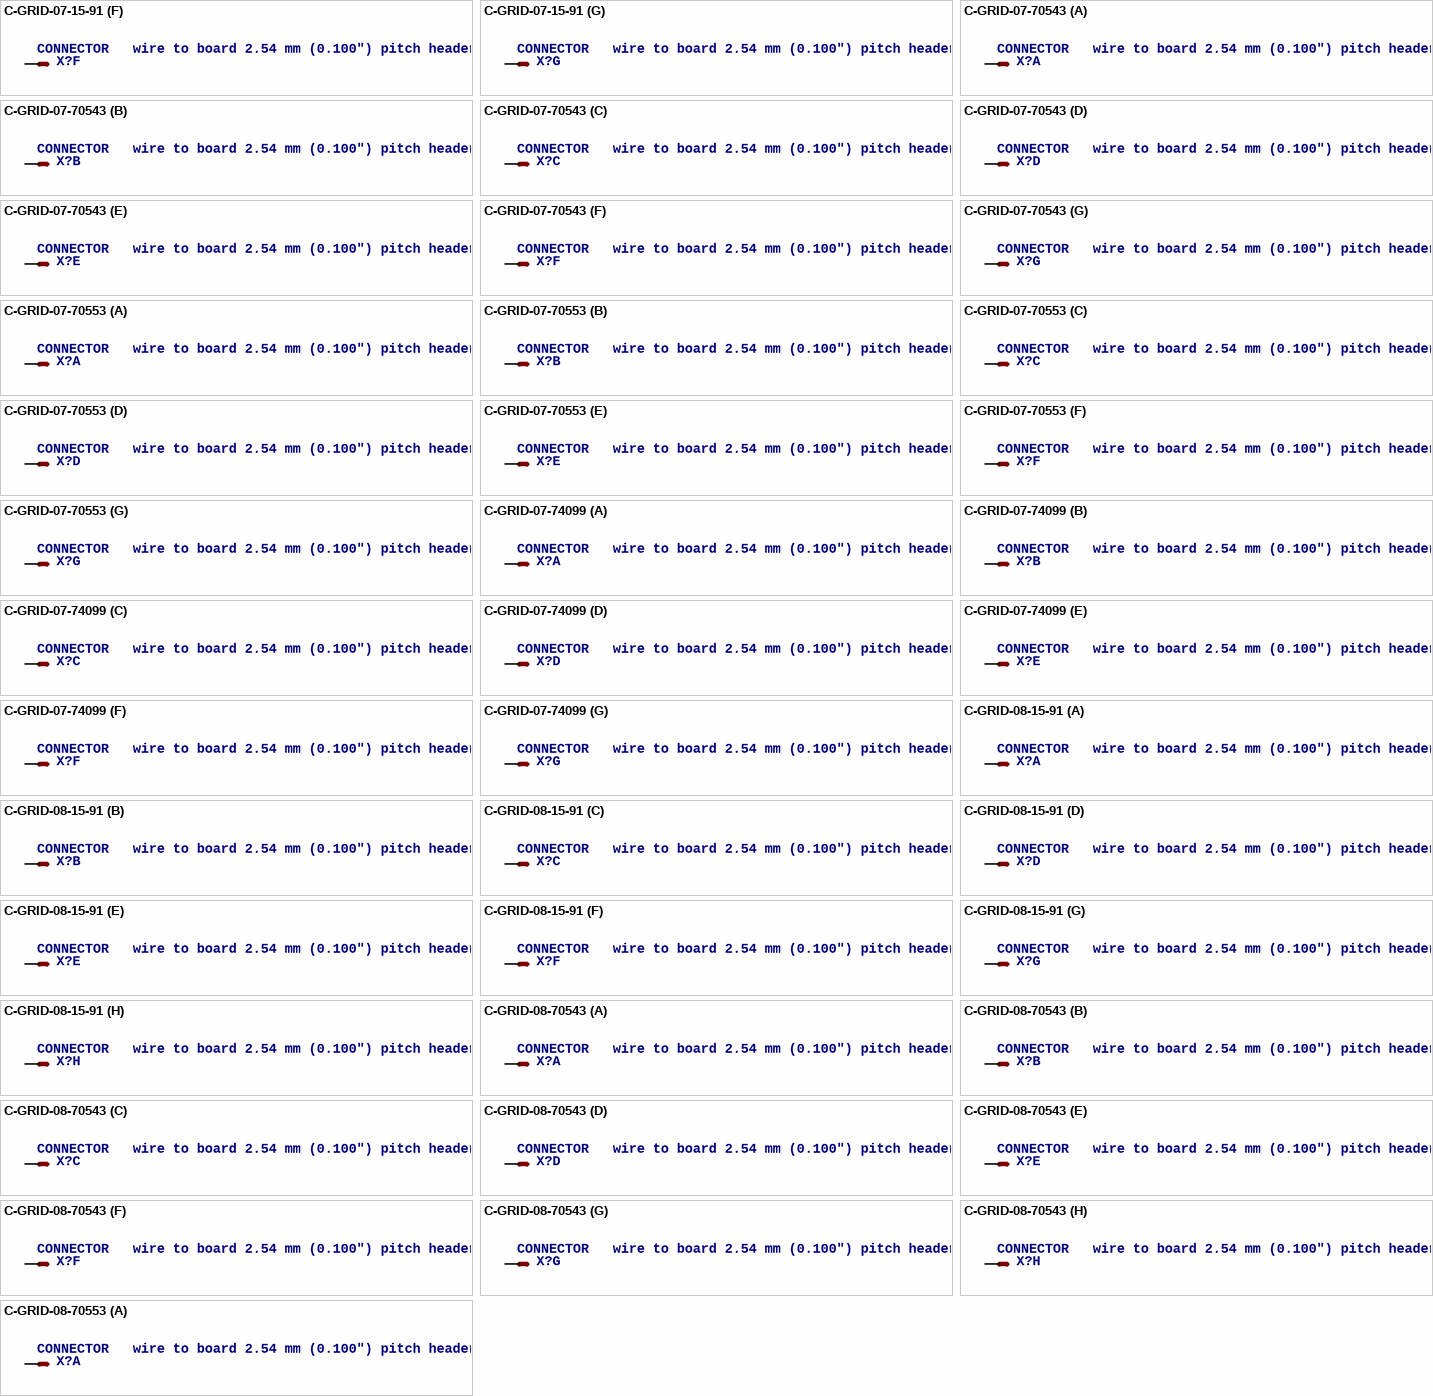
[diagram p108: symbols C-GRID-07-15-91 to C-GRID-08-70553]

## C-GRID-07-15-91
designator X?, comment CONNECTOR   wire to board 2.54 mm (0.100") pitch header
footprint 15-91-07
part A pins: 1 S
part B pins: 2 S
part C pins: 3 S
part D pins: 4 S
part E pins: 5 S
part F pins: 6 S
part G pins: 7 S

## C-GRID-07-70543
designator X?, comment CONNECTOR   wire to board 2.54 mm (0.100") pitch header
footprint 70543-07
part A pins: 1 S
part B pins: 2 S
part C pins: 3 S
part D pins: 4 S
part E pins: 5 S
part F pins: 6 S
part G pins: 7 S

## C-GRID-07-70553
designator X?, comment CONNECTOR   wire to board 2.54 mm (0.100") pitch header
footprint 70553-07
part A pins: 1 S
part B pins: 2 S
part C pins: 3 S
part D pins: 4 S
part E pins: 5 S
part F pins: 6 S
part G pins: 7 S

## C-GRID-07-74099
designator X?, comment CONNECTOR   wire to board 2.54 mm (0.100") pitch header
footprint 74099-07
part A pins: 1 S
part B pins: 2 S
part C pins: 3 S
part D pins: 4 S
part E pins: 5 S
part F pins: 6 S
part G pins: 7 S

## C-GRID-08-15-91
designator X?, comment CONNECTOR   wire to board 2.54 mm (0.100") pitch header
footprint 15-91-08
part A pins: 1 S
part B pins: 2 S
part C pins: 3 S
part D pins: 4 S
part E pins: 5 S
part F pins: 6 S
part G pins: 7 S
part H pins: 8 S

## C-GRID-08-70543
designator X?, comment CONNECTOR   wire to board 2.54 mm (0.100") pitch header
footprint 70543-08
part A pins: 1 S
part B pins: 2 S
part C pins: 3 S
part D pins: 4 S
part E pins: 5 S
part F pins: 6 S
part G pins: 7 S
part H pins: 8 S

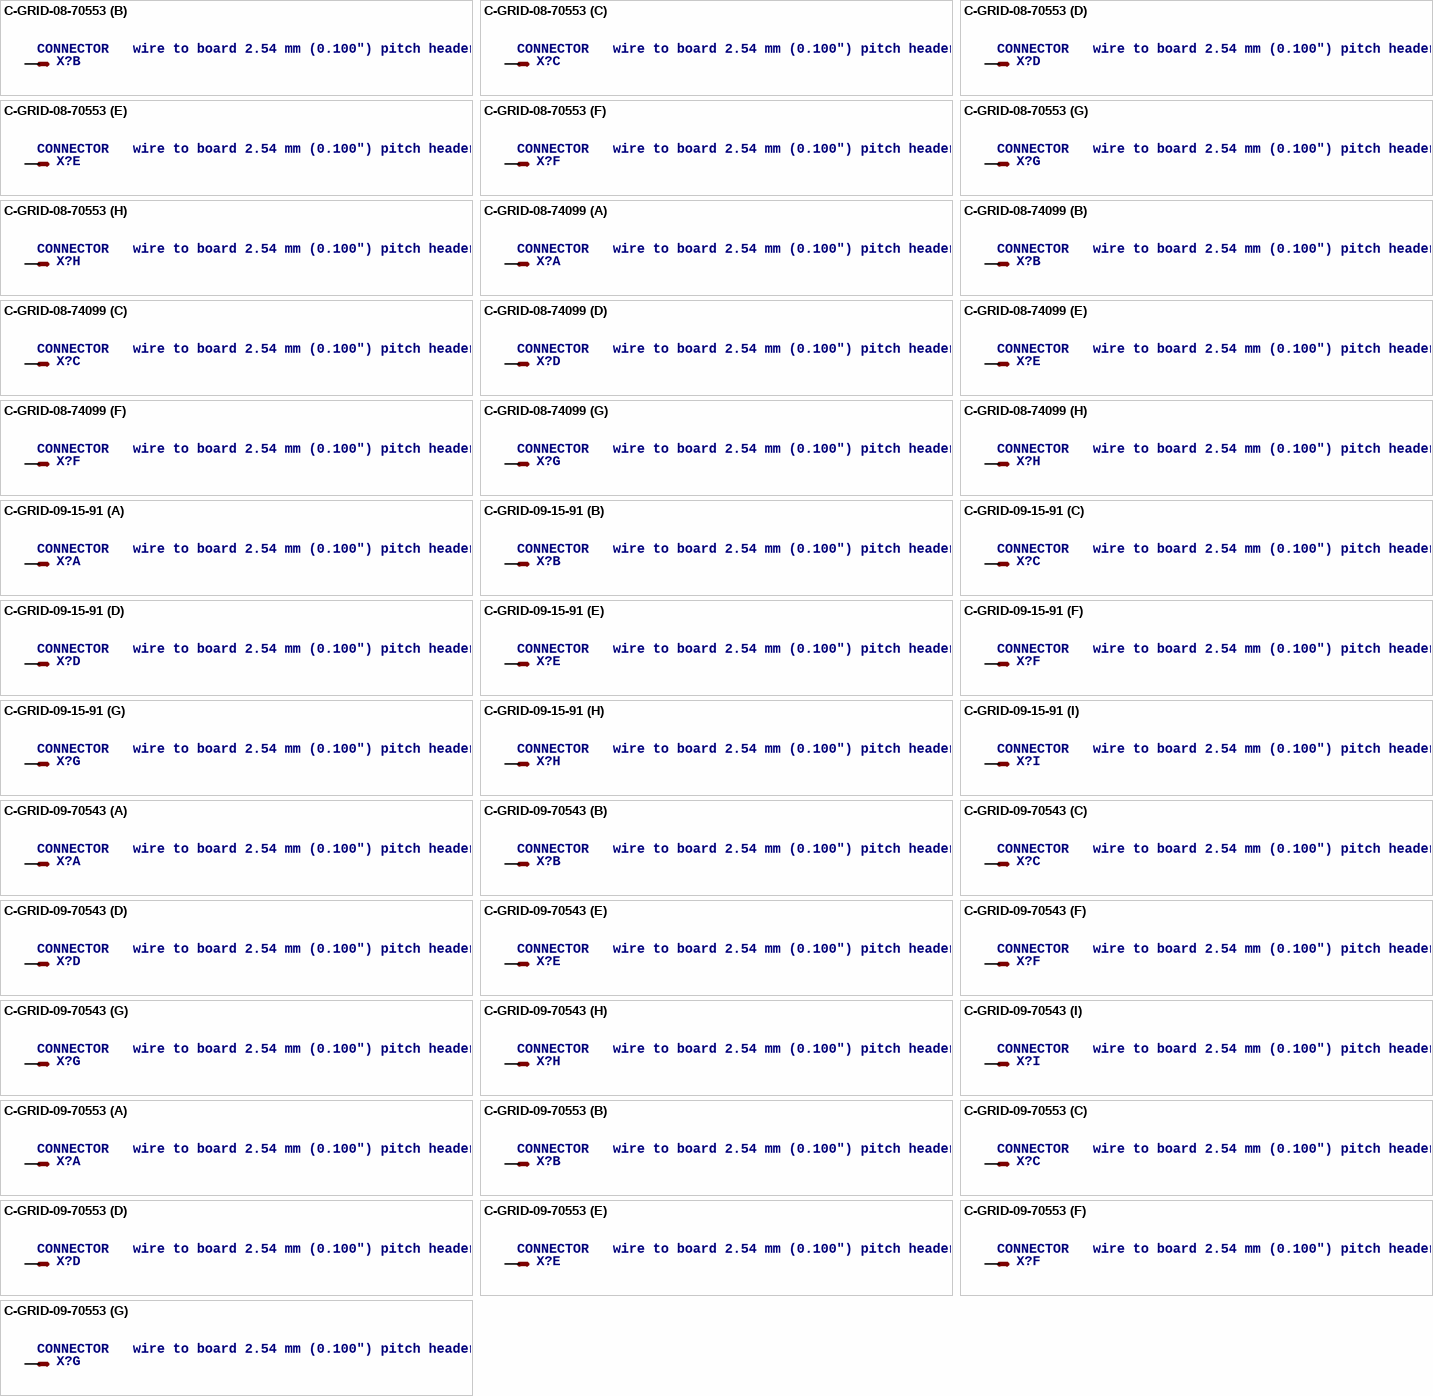
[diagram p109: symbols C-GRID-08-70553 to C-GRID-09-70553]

## C-GRID-08-70553
designator X?, comment CONNECTOR   wire to board 2.54 mm (0.100") pitch header
footprint 70553-08
part A pins: 1 S
part B pins: 2 S
part C pins: 3 S
part D pins: 4 S
part E pins: 5 S
part F pins: 6 S
part G pins: 7 S
part H pins: 8 S

## C-GRID-08-74099
designator X?, comment CONNECTOR   wire to board 2.54 mm (0.100") pitch header
footprint 74099-08
part A pins: 1 S
part B pins: 2 S
part C pins: 3 S
part D pins: 4 S
part E pins: 5 S
part F pins: 6 S
part G pins: 7 S
part H pins: 8 S

## C-GRID-09-15-91
designator X?, comment CONNECTOR   wire to board 2.54 mm (0.100") pitch header
footprint 15-91-09
part A pins: 1 S
part B pins: 2 S
part C pins: 3 S
part D pins: 4 S
part E pins: 5 S
part F pins: 6 S
part G pins: 7 S
part H pins: 8 S
part I pins: 9 S

## C-GRID-09-70543
designator X?, comment CONNECTOR   wire to board 2.54 mm (0.100") pitch header
footprint 70543-09
part A pins: 1 S
part B pins: 2 S
part C pins: 3 S
part D pins: 4 S
part E pins: 5 S
part F pins: 6 S
part G pins: 7 S
part H pins: 8 S
part I pins: 9 S

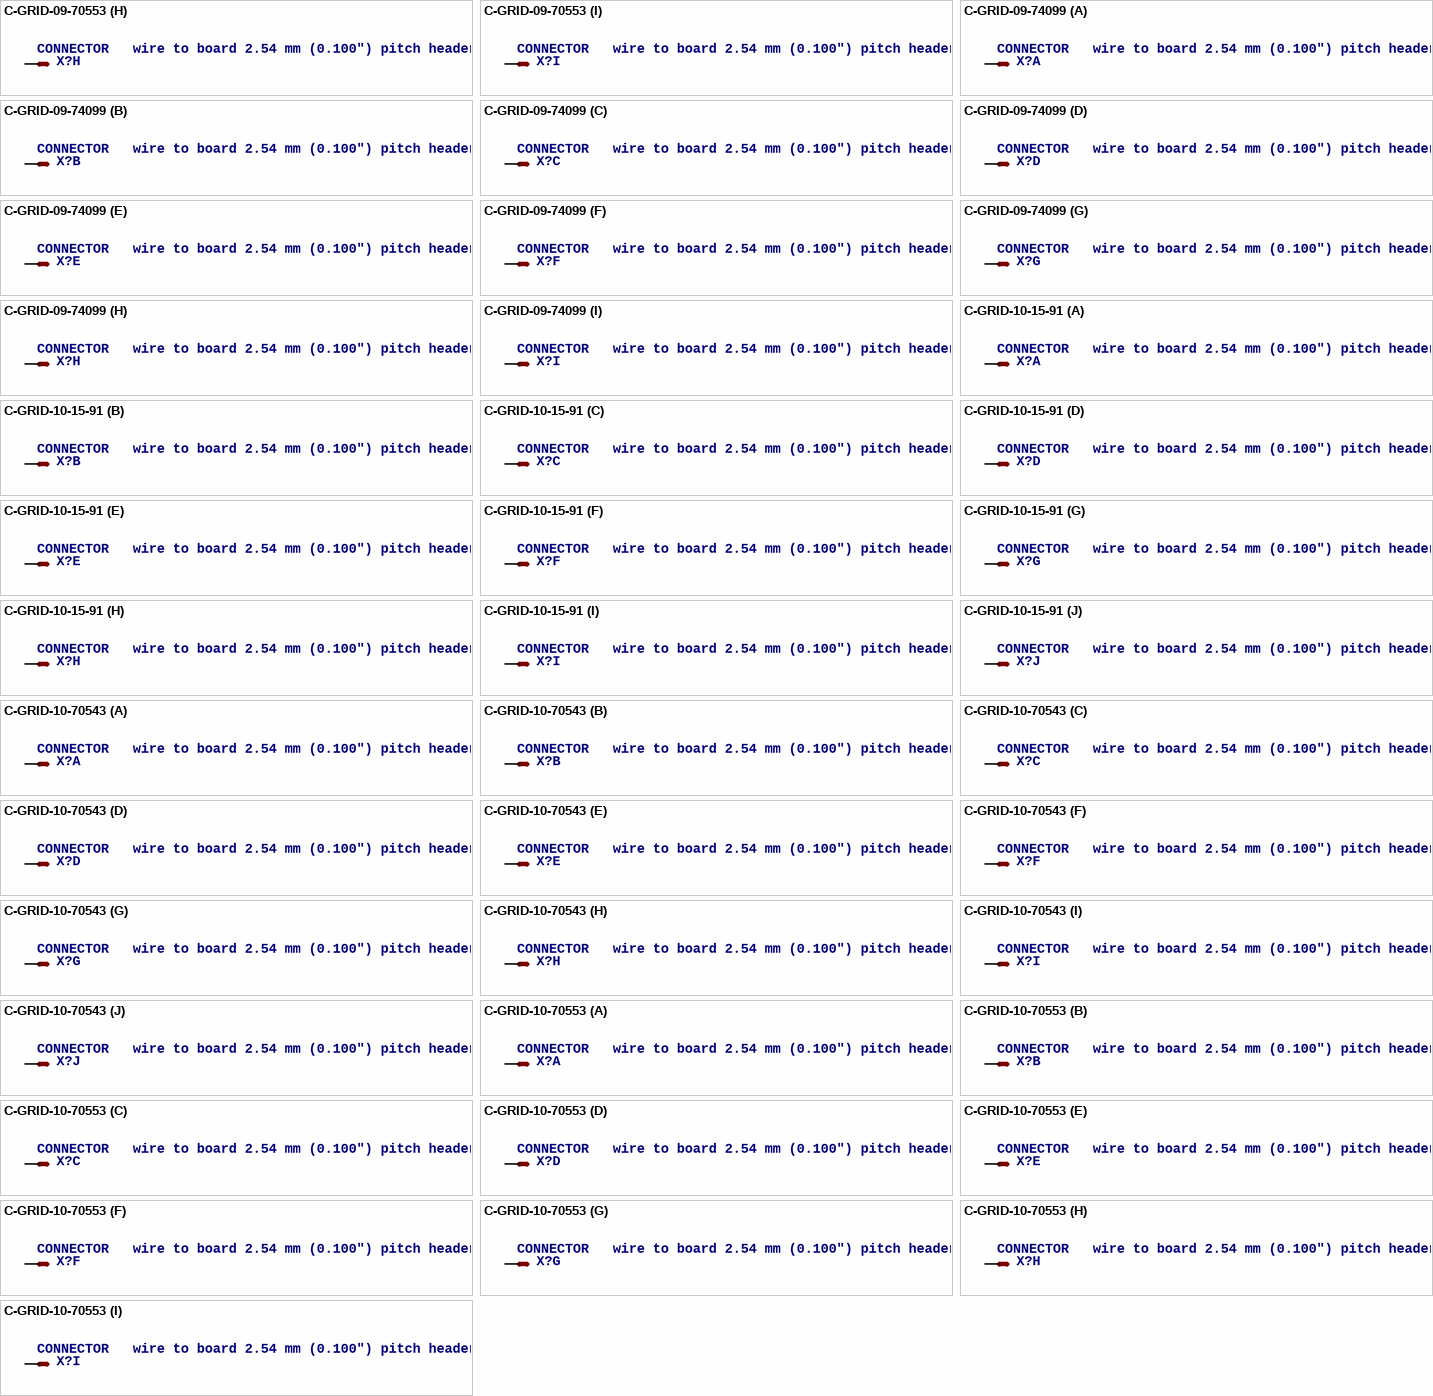
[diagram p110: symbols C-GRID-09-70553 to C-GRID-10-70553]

## C-GRID-09-70553
designator X?, comment CONNECTOR   wire to board 2.54 mm (0.100") pitch header
footprint 70553-09
part A pins: 1 S
part B pins: 2 S
part C pins: 3 S
part D pins: 4 S
part E pins: 5 S
part F pins: 6 S
part G pins: 7 S
part H pins: 8 S
part I pins: 9 S

## C-GRID-09-74099
designator X?, comment CONNECTOR   wire to board 2.54 mm (0.100") pitch header
footprint 74099-09
part A pins: 1 S
part B pins: 2 S
part C pins: 3 S
part D pins: 4 S
part E pins: 5 S
part F pins: 6 S
part G pins: 7 S
part H pins: 8 S
part I pins: 9 S

## C-GRID-10-15-91
designator X?, comment CONNECTOR   wire to board 2.54 mm (0.100") pitch header
footprint 15-91-10
part A pins: 1 S
part B pins: 2 S
part C pins: 3 S
part D pins: 4 S
part E pins: 5 S
part F pins: 6 S
part G pins: 7 S
part H pins: 8 S
part I pins: 9 S
part J pins: 10 S

## C-GRID-10-70543
designator X?, comment CONNECTOR   wire to board 2.54 mm (0.100") pitch header
footprint 70543-10
part A pins: 1 S
part B pins: 2 S
part C pins: 3 S
part D pins: 4 S
part E pins: 5 S
part F pins: 6 S
part G pins: 7 S
part H pins: 8 S
part I pins: 9 S
part J pins: 10 S

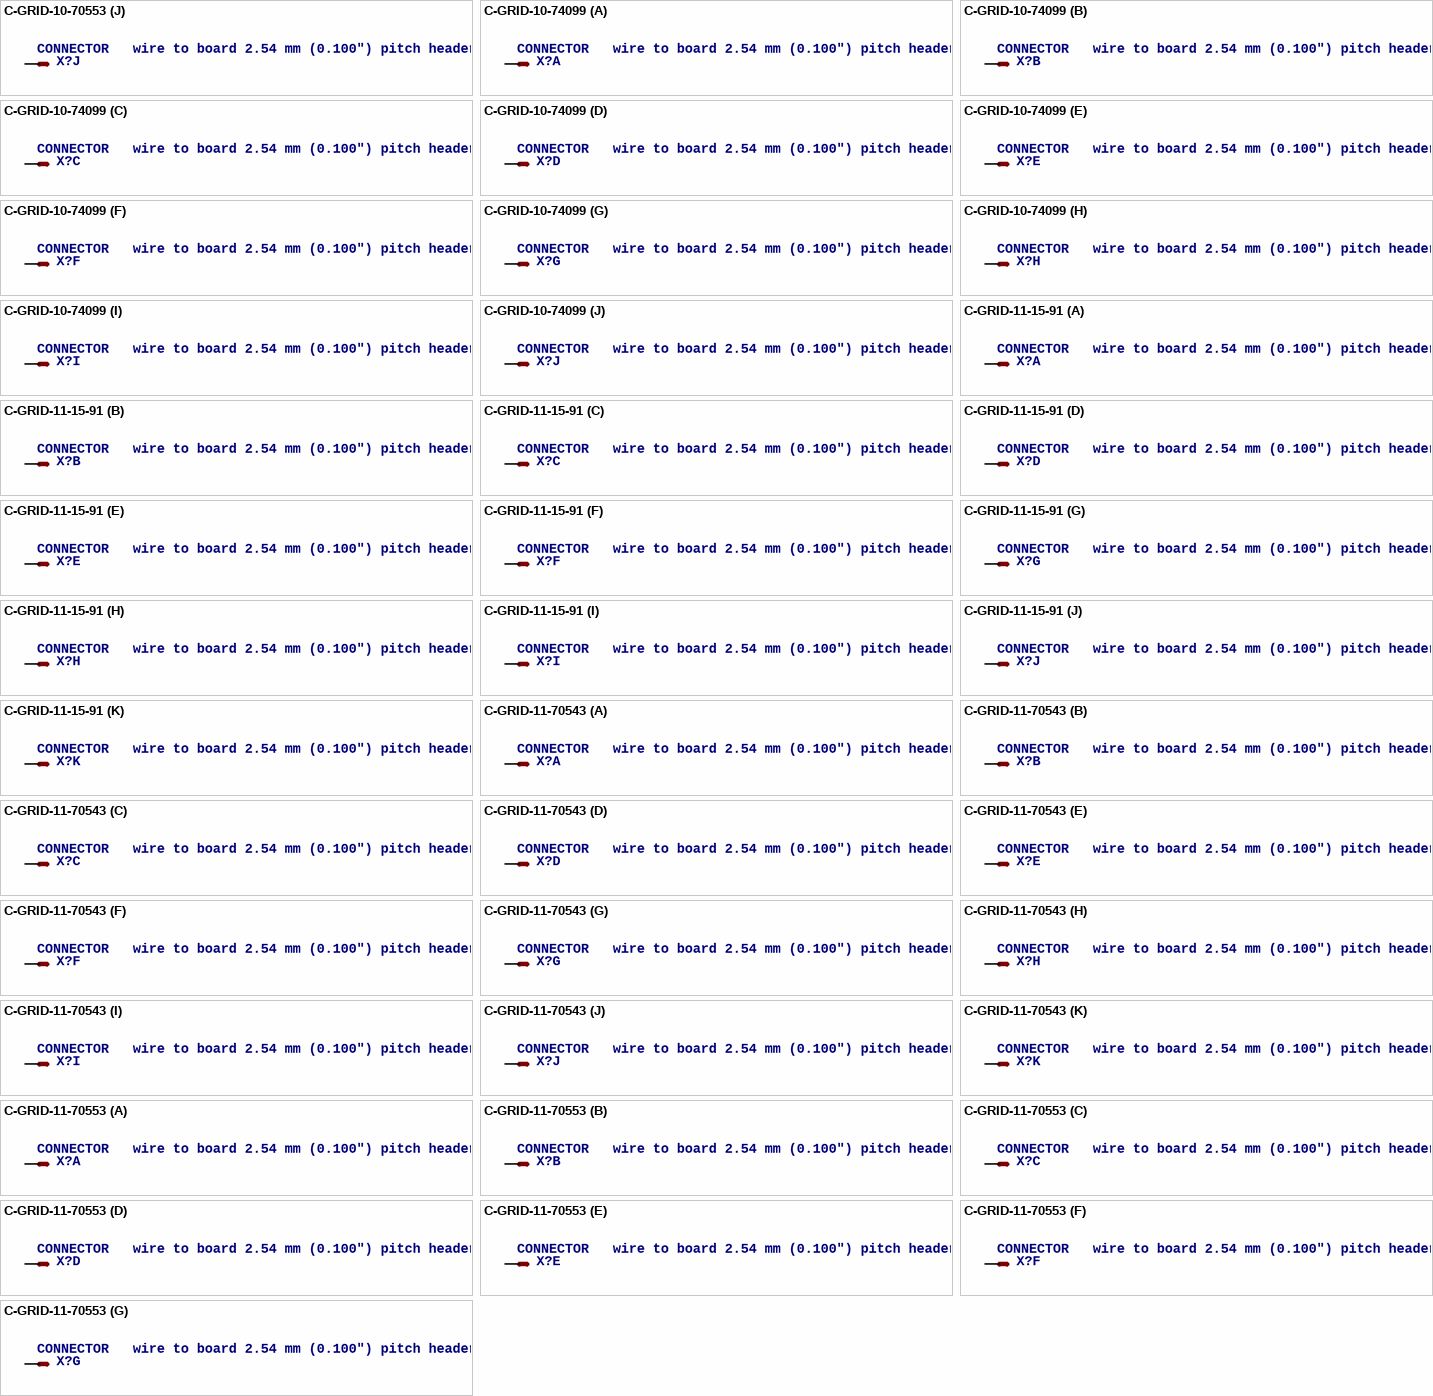
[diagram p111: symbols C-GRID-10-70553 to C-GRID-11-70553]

## C-GRID-10-70553
designator X?, comment CONNECTOR   wire to board 2.54 mm (0.100") pitch header
footprint 70553-10
part A pins: 1 S
part B pins: 2 S
part C pins: 3 S
part D pins: 4 S
part E pins: 5 S
part F pins: 6 S
part G pins: 7 S
part H pins: 8 S
part I pins: 9 S
part J pins: 10 S

## C-GRID-10-74099
designator X?, comment CONNECTOR   wire to board 2.54 mm (0.100") pitch header
footprint 74099-10
part A pins: 1 S
part B pins: 2 S
part C pins: 3 S
part D pins: 4 S
part E pins: 5 S
part F pins: 6 S
part G pins: 7 S
part H pins: 8 S
part I pins: 9 S
part J pins: 10 S

## C-GRID-11-15-91
designator X?, comment CONNECTOR   wire to board 2.54 mm (0.100") pitch header
footprint 15-91-11
part A pins: 1 S
part B pins: 2 S
part C pins: 3 S
part D pins: 4 S
part E pins: 5 S
part F pins: 6 S
part G pins: 7 S
part H pins: 8 S
part I pins: 9 S
part J pins: 10 S
part K pins: 11 S

## C-GRID-11-70543
designator X?, comment CONNECTOR   wire to board 2.54 mm (0.100") pitch header
footprint 70543-11
part A pins: 1 S
part B pins: 2 S
part C pins: 3 S
part D pins: 4 S
part E pins: 5 S
part F pins: 6 S
part G pins: 7 S
part H pins: 8 S
part I pins: 9 S
part J pins: 10 S
part K pins: 11 S

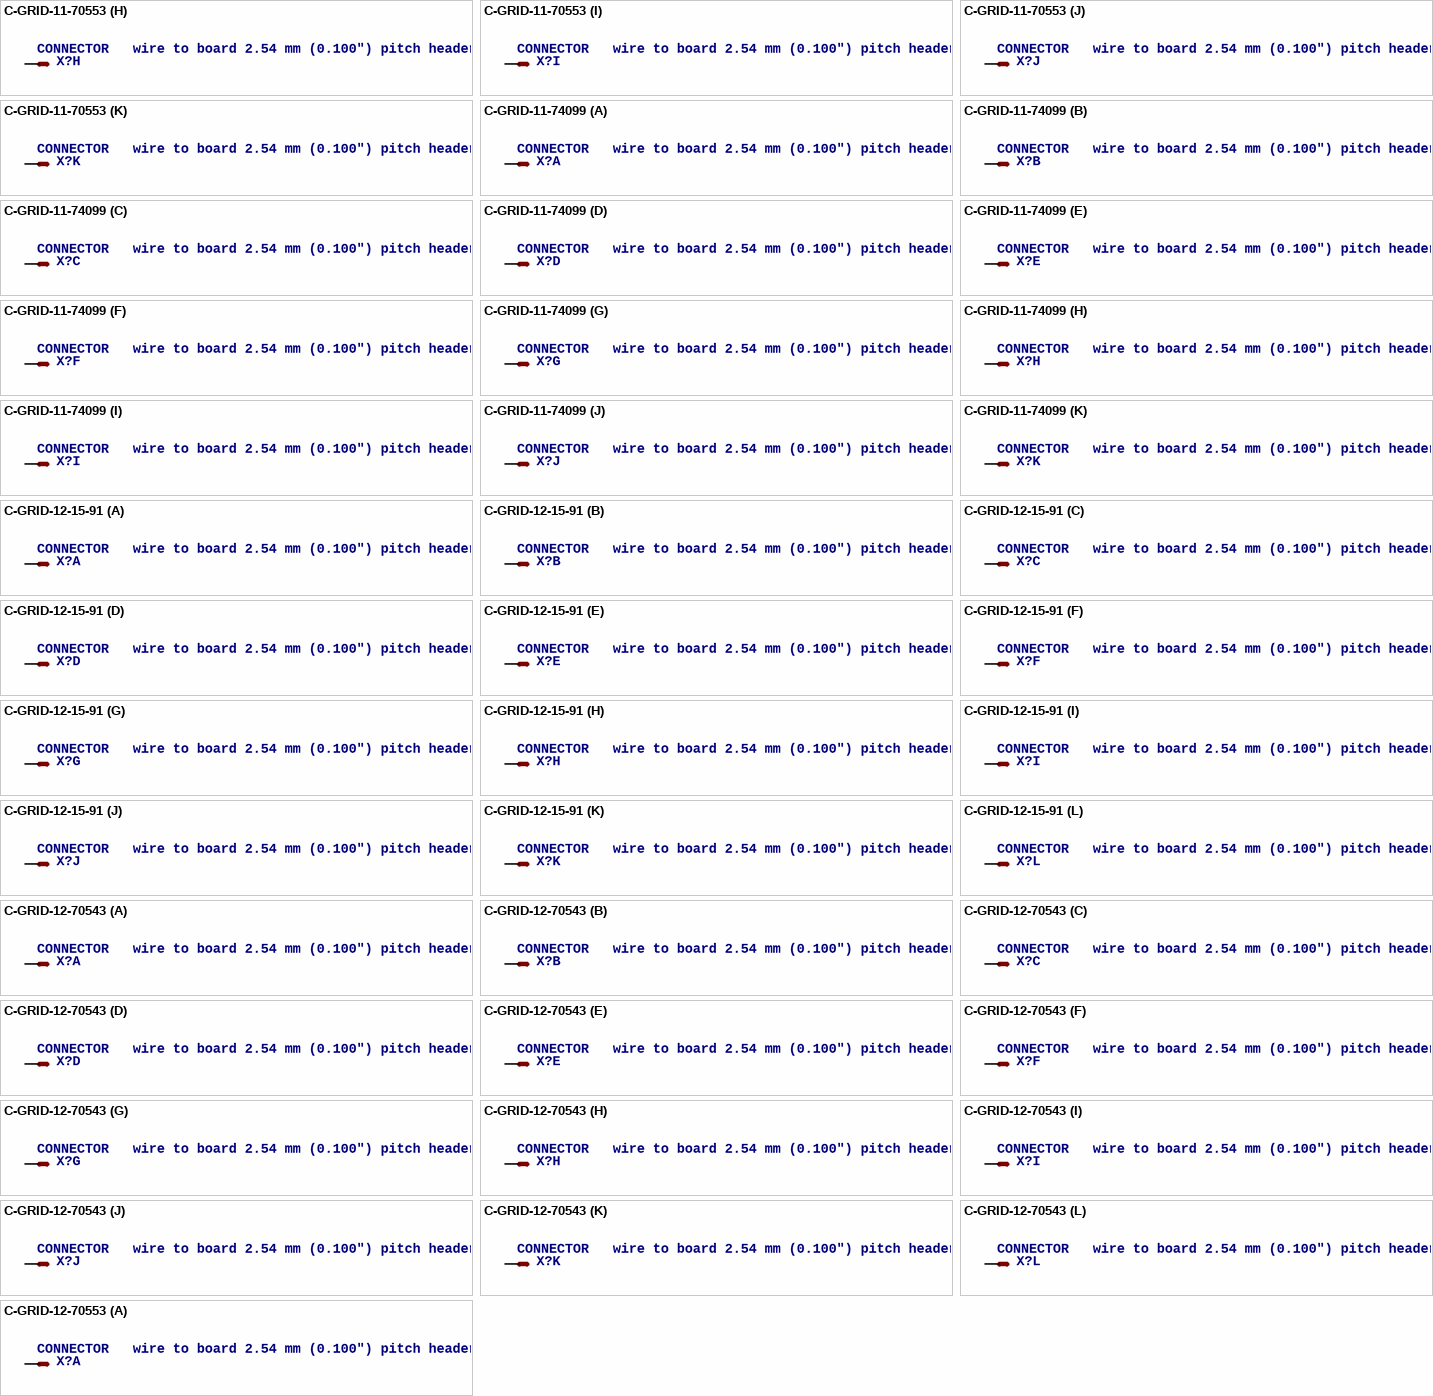
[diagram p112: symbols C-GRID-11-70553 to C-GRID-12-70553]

## C-GRID-11-70553
designator X?, comment CONNECTOR   wire to board 2.54 mm (0.100") pitch header
footprint 70553-11
part A pins: 1 S
part B pins: 2 S
part C pins: 3 S
part D pins: 4 S
part E pins: 5 S
part F pins: 6 S
part G pins: 7 S
part H pins: 8 S
part I pins: 9 S
part J pins: 10 S
part K pins: 11 S

## C-GRID-11-74099
designator X?, comment CONNECTOR   wire to board 2.54 mm (0.100") pitch header
footprint 74099-11
part A pins: 1 S
part B pins: 2 S
part C pins: 3 S
part D pins: 4 S
part E pins: 5 S
part F pins: 6 S
part G pins: 7 S
part H pins: 8 S
part I pins: 9 S
part J pins: 10 S
part K pins: 11 S

## C-GRID-12-15-91
designator X?, comment CONNECTOR   wire to board 2.54 mm (0.100") pitch header
footprint 15-91-12
part A pins: 1 S
part B pins: 2 S
part C pins: 3 S
part D pins: 4 S
part E pins: 5 S
part F pins: 6 S
part G pins: 7 S
part H pins: 8 S
part I pins: 9 S
part J pins: 10 S
part K pins: 11 S
part L pins: 12 S

## C-GRID-12-70543
designator X?, comment CONNECTOR   wire to board 2.54 mm (0.100") pitch header
footprint 70543-12
part A pins: 1 S
part B pins: 2 S
part C pins: 3 S
part D pins: 4 S
part E pins: 5 S
part F pins: 6 S
part G pins: 7 S
part H pins: 8 S
part I pins: 9 S
part J pins: 10 S
part K pins: 11 S
part L pins: 12 S

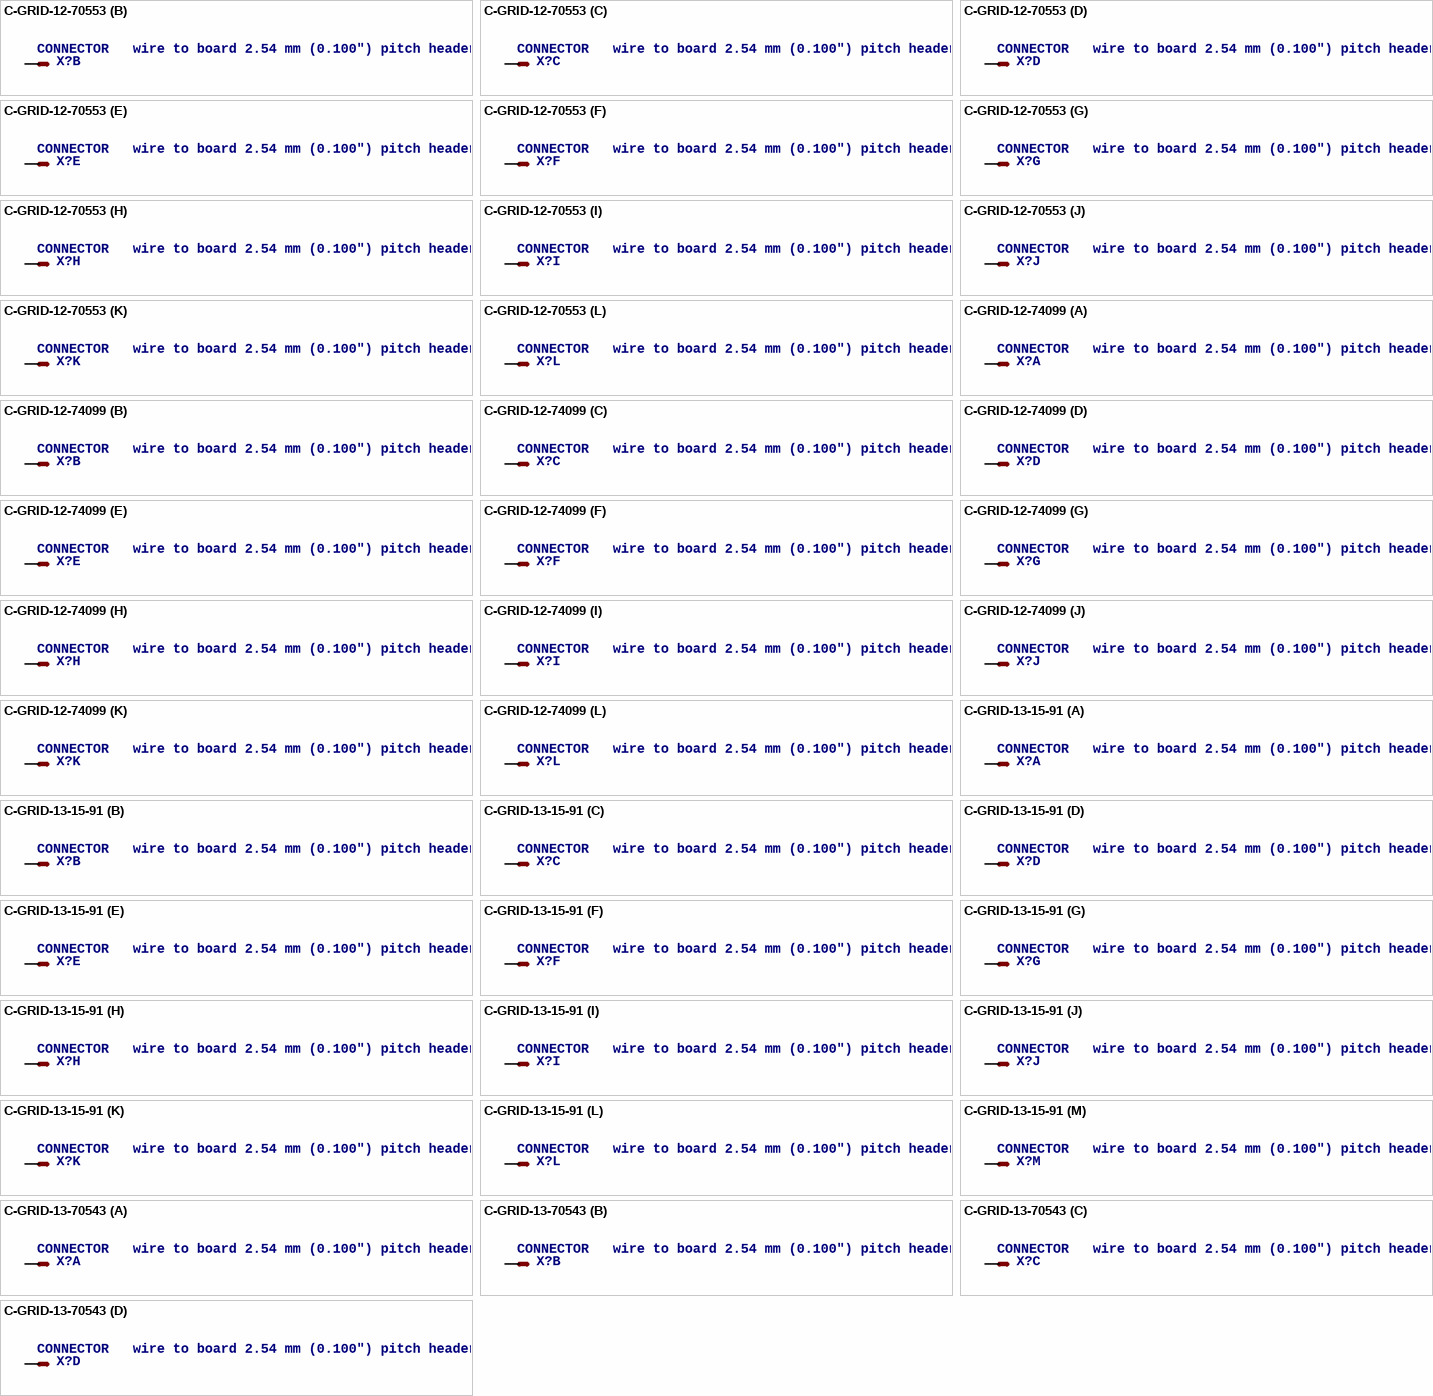
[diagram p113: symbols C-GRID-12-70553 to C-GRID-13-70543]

## C-GRID-12-70553
designator X?, comment CONNECTOR   wire to board 2.54 mm (0.100") pitch header
footprint 70553-12
part A pins: 1 S
part B pins: 2 S
part C pins: 3 S
part D pins: 4 S
part E pins: 5 S
part F pins: 6 S
part G pins: 7 S
part H pins: 8 S
part I pins: 9 S
part J pins: 10 S
part K pins: 11 S
part L pins: 12 S

## C-GRID-12-74099
designator X?, comment CONNECTOR   wire to board 2.54 mm (0.100") pitch header
footprint 74099-12
part A pins: 1 S
part B pins: 2 S
part C pins: 3 S
part D pins: 4 S
part E pins: 5 S
part F pins: 6 S
part G pins: 7 S
part H pins: 8 S
part I pins: 9 S
part J pins: 10 S
part K pins: 11 S
part L pins: 12 S

## C-GRID-13-15-91
designator X?, comment CONNECTOR   wire to board 2.54 mm (0.100") pitch header
footprint 15-91-13
part A pins: 1 S
part B pins: 2 S
part C pins: 3 S
part D pins: 4 S
part E pins: 5 S
part F pins: 6 S
part G pins: 7 S
part H pins: 8 S
part I pins: 9 S
part J pins: 10 S
part K pins: 11 S
part L pins: 12 S
part M pins: 13 S

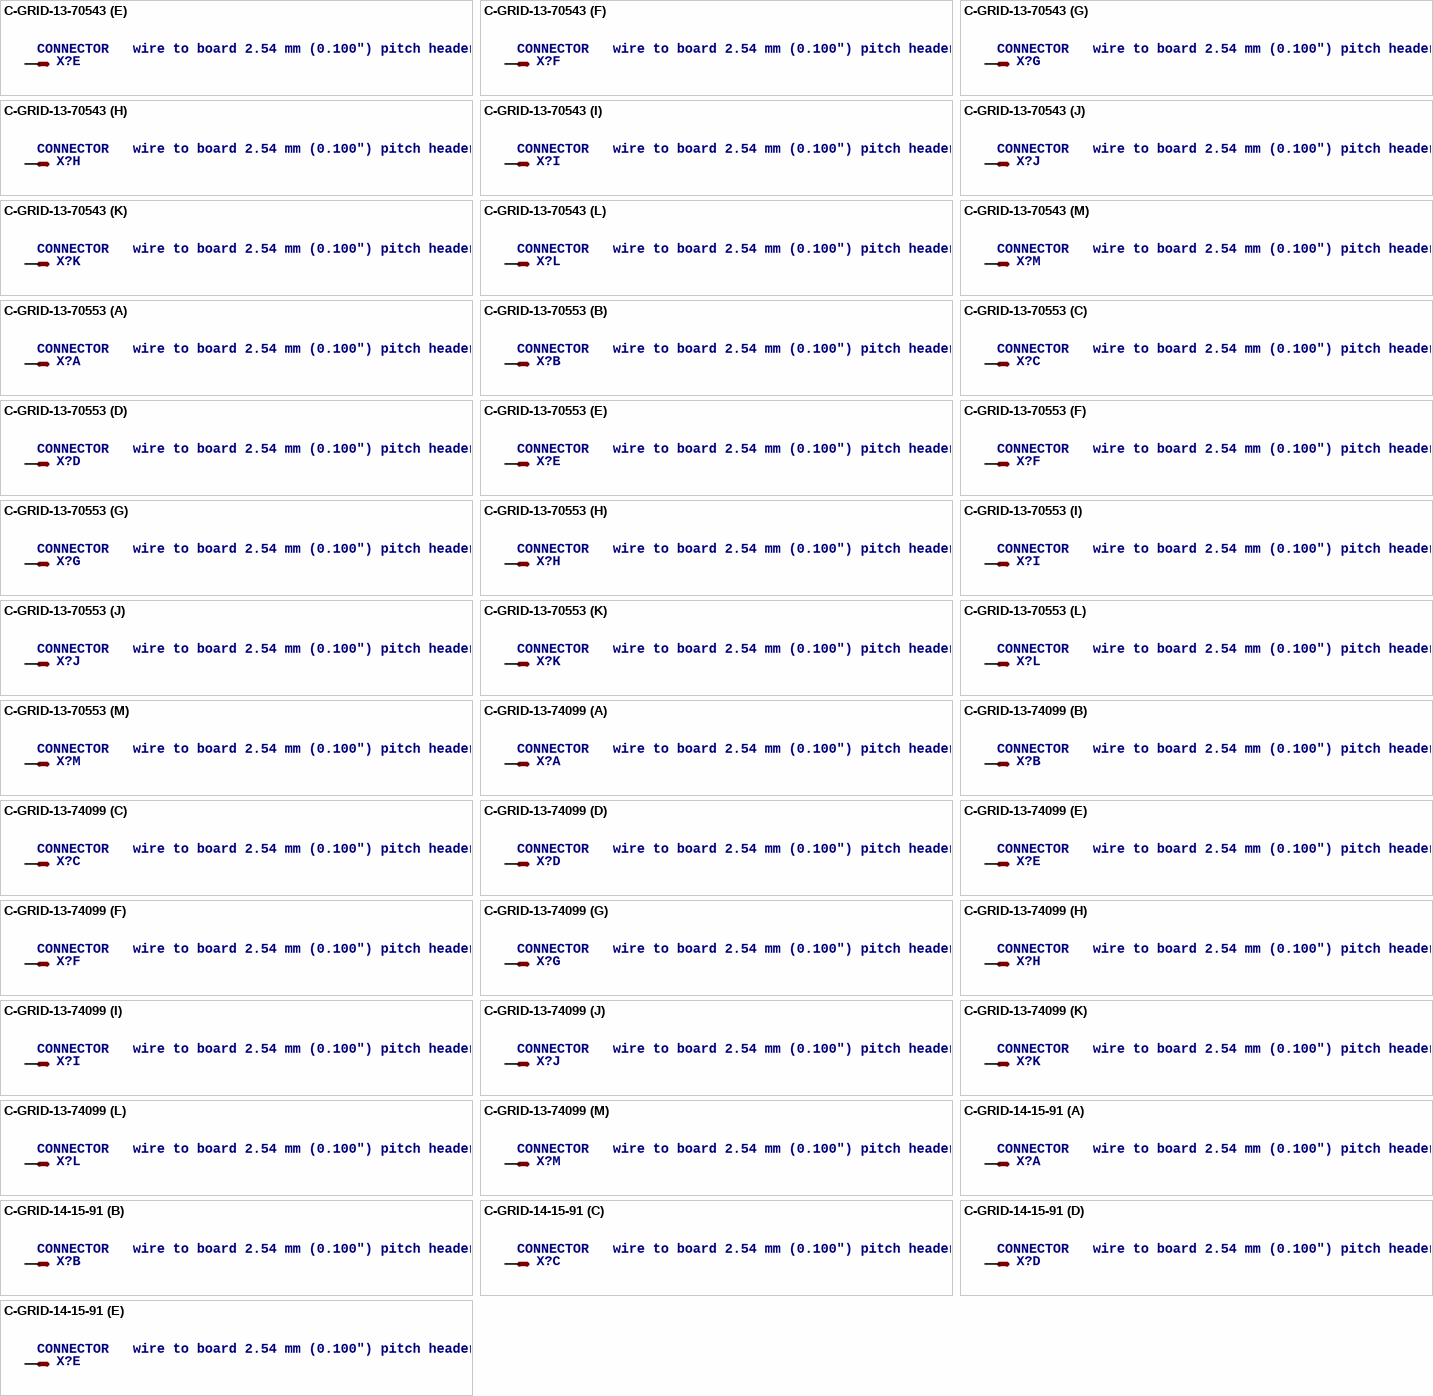
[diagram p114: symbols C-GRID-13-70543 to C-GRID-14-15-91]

## C-GRID-13-70543
designator X?, comment CONNECTOR   wire to board 2.54 mm (0.100") pitch header
footprint 70543-13
part A pins: 1 S
part B pins: 2 S
part C pins: 3 S
part D pins: 4 S
part E pins: 5 S
part F pins: 6 S
part G pins: 7 S
part H pins: 8 S
part I pins: 9 S
part J pins: 10 S
part K pins: 11 S
part L pins: 12 S
part M pins: 13 S

## C-GRID-13-70553
designator X?, comment CONNECTOR   wire to board 2.54 mm (0.100") pitch header
footprint 70553-13
part A pins: 1 S
part B pins: 2 S
part C pins: 3 S
part D pins: 4 S
part E pins: 5 S
part F pins: 6 S
part G pins: 7 S
part H pins: 8 S
part I pins: 9 S
part J pins: 10 S
part K pins: 11 S
part L pins: 12 S
part M pins: 13 S

## C-GRID-13-74099
designator X?, comment CONNECTOR   wire to board 2.54 mm (0.100") pitch header
footprint 74099-13
part A pins: 1 S
part B pins: 2 S
part C pins: 3 S
part D pins: 4 S
part E pins: 5 S
part F pins: 6 S
part G pins: 7 S
part H pins: 8 S
part I pins: 9 S
part J pins: 10 S
part K pins: 11 S
part L pins: 12 S
part M pins: 13 S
